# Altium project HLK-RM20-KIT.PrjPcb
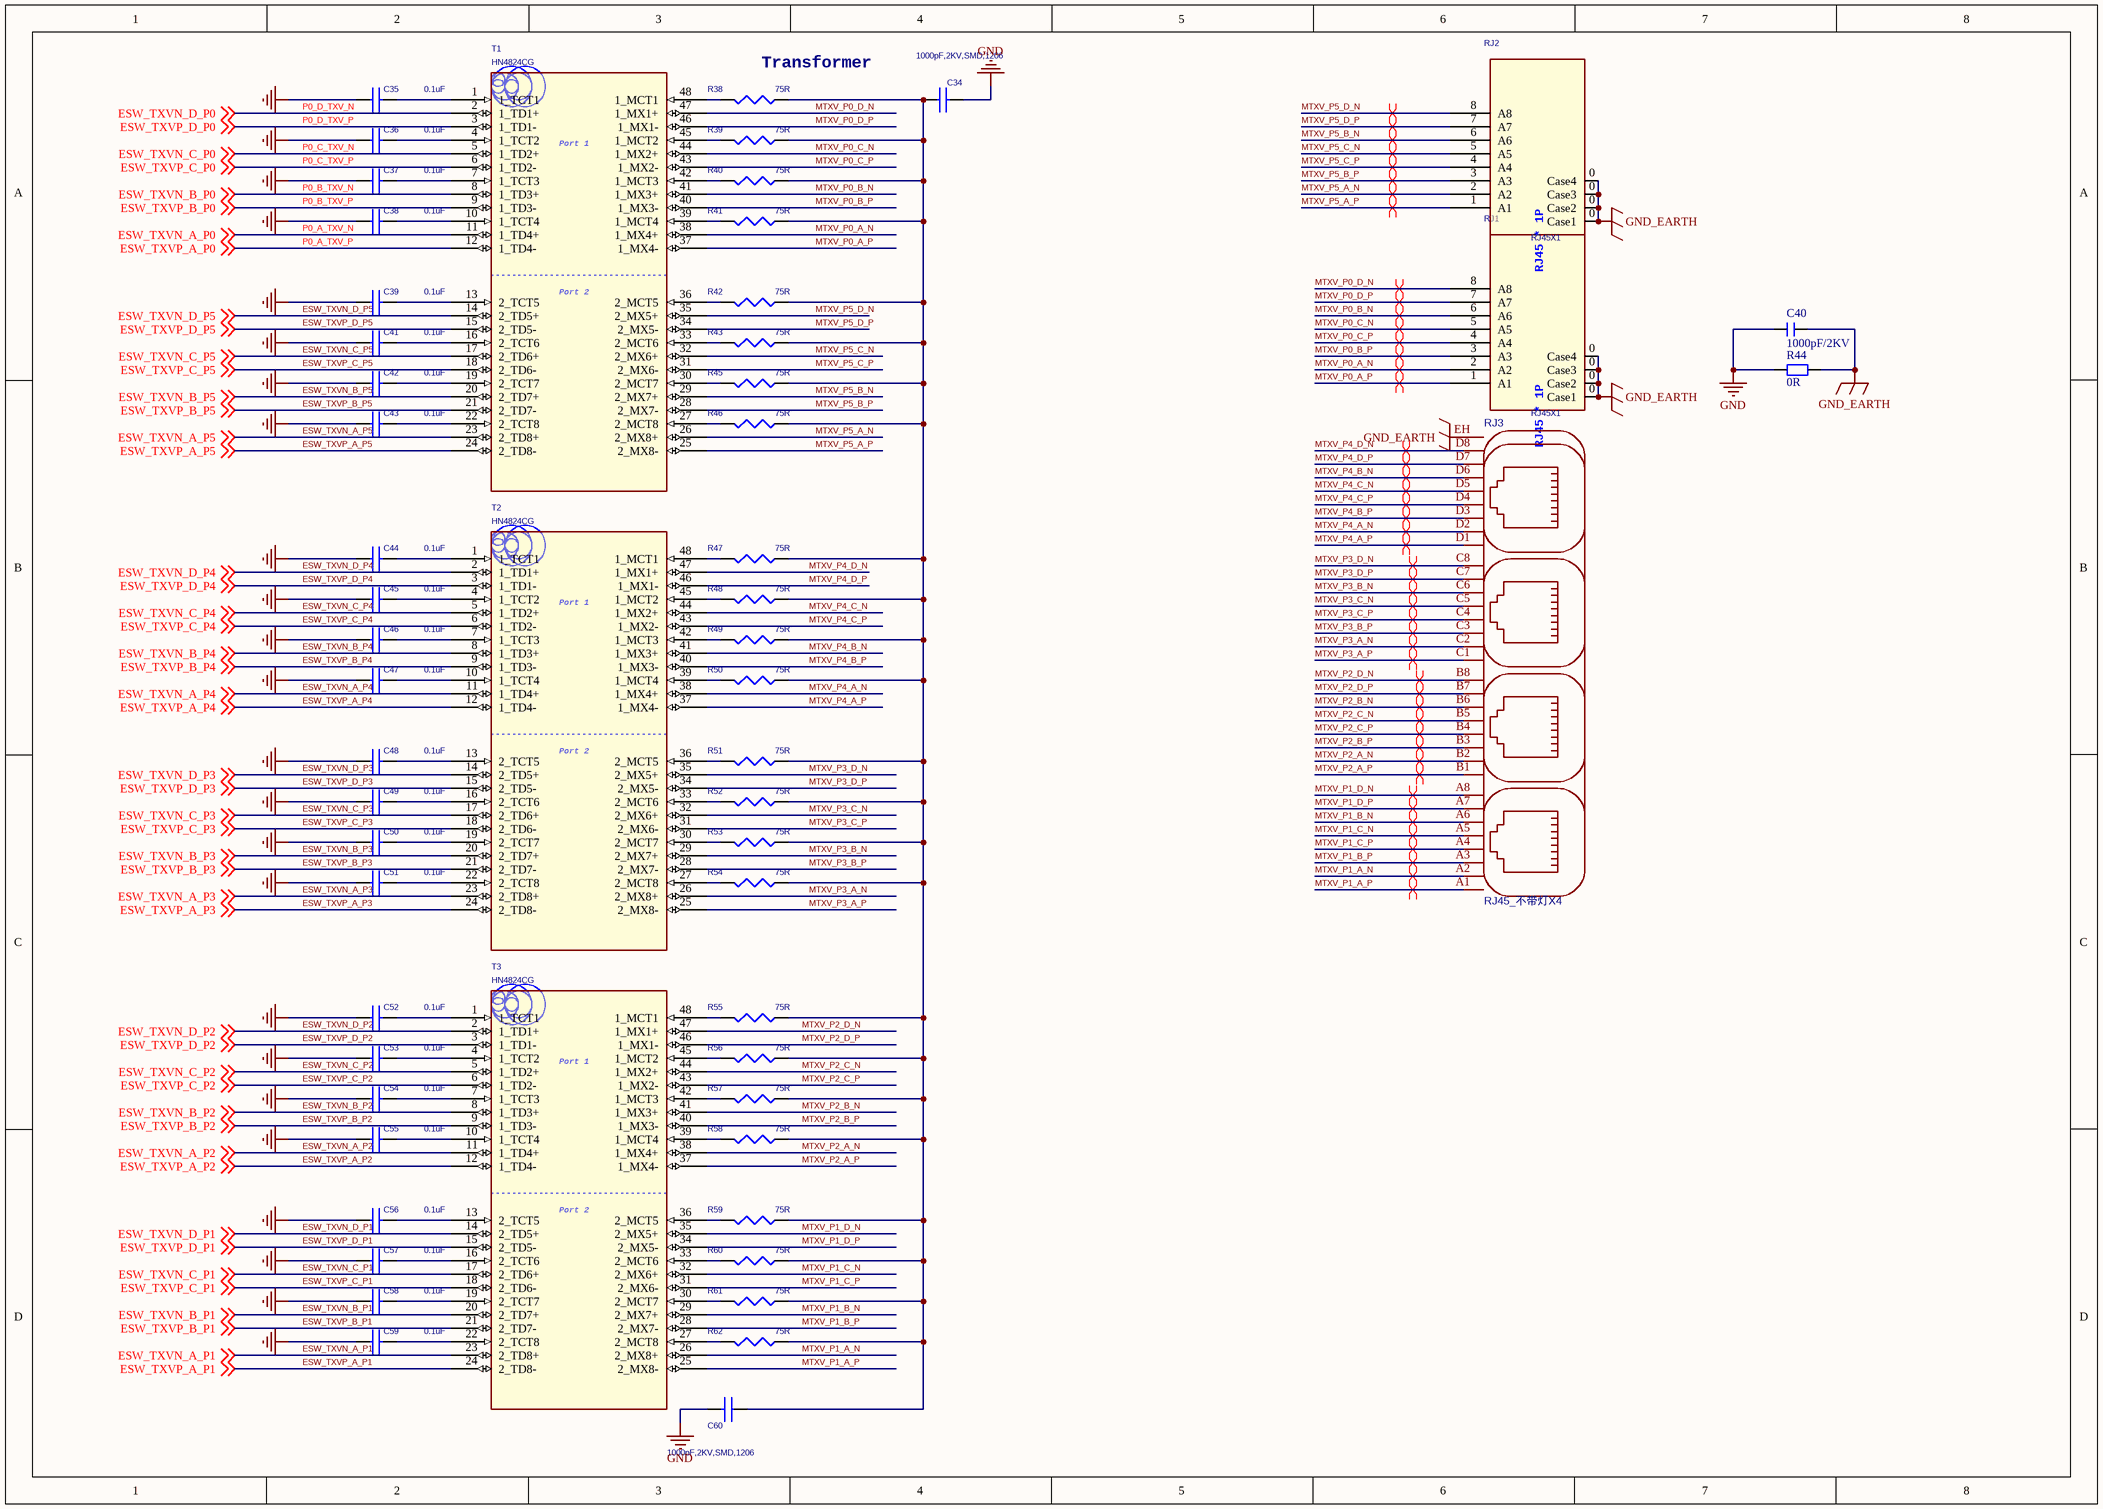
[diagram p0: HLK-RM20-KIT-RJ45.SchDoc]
4 sheets, 212 parts. Net scope: global (net labels, ports and power ports of the same name join across sheets).
Board file: HLK-RM20-KIT.PcbDoc
Sheets:
  HLK-RM20-KIT-RJ45.SchDoc
  HLK-RM20-KIT-4G.SchDoc
  HLK-RM20-KIT-5G.SchDoc
  HLK-RM20-KIT-POWER_LED.SchDoc

## Sheet HLK-RM20-KIT-RJ45.SchDoc
size A3

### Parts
C34  1000pF,2KV,SMD,1206  [C 1206_L]
C35  0.1uF  [C 0402_L]
C36  0.1uF  [C 0402_L]
C37  0.1uF  [C 0402_L]
C38  0.1uF  [C 0402_L]
C39  0.1uF  [C 0402_L]
C40  1000pF/2KV  [C 1206_L]
C41  0.1uF  [C 0402_L]
C42  0.1uF  [C 0402_L]
C43  0.1uF  [C 0402_L]
C44  0.1uF  [C 0402_L]
C45  0.1uF  [C 0402_L]
C46  0.1uF  [C 0402_L]
C47  0.1uF  [C 0402_L]
C48  0.1uF  [C 0402_L]
C49  0.1uF  [C 0402_L]
C50  0.1uF  [C 0402_L]
C51  0.1uF  [C 0402_L]
C52  0.1uF  [C 0402_L]
C53  0.1uF  [C 0402_L]
C54  0.1uF  [C 0402_L]
C55  0.1uF  [C 0402_L]
C56  0.1uF  [C 0402_L]
C57  0.1uF  [C 0402_L]
C58  0.1uF  [C 0402_L]
C59  0.1uF  [C 0402_L]
C60  1000pF,2KV,SMD,1206  [C 1206_L]
R38  75R  [R 0402_L]
R39  75R  [R 0402_L]
R40  75R  [R 0402_L]
R41  75R  [R 0402_L]
R42  75R  [R 0402_L]
R43  75R  [R 0402_L]
R44  0R  [R 1206_L]
R45  75R  [R 0402_L]
R46  75R  [R 0402_L]
R47  75R  [R 0402_L]
R48  75R  [R 0402_L]
R49  75R  [R 0402_L]
R50  75R  [R 0402_L]
R51  75R  [R 0402_L]
R52  75R  [R 0402_L]
R53  75R  [R 0402_L]
R54  75R  [R 0402_L]
R55  75R  [R 0402_L]
R56  75R  [R 0402_L]
R57  75R  [R 0402_L]
R58  75R  [R 0402_L]
R59  75R  [R 0402_L]
R60  75R  [R 0402_L]
R61  75R  [R 0402_L]
R62  75R  [R 0402_L]
RJ1  RJ45X1  [RJ45_网口不带灯X1]
RJ2  RJ45X1  [RJ45_网口不带灯X1]
RJ3  RJ45_不带灯X4  [RJ45_网口不带灯X4]
T1  HN4824CG  [TRANSFORMER/48P/SMD/GS5014LF]
T2  HN4824CG  [TRANSFORMER/48P/SMD/GS5014LF]
T3  HN4824CG  [TRANSFORMER/48P/SMD/GS5014LF]

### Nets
GND: C34.2 C35.1 C36.1 C37.1 C38.1 C39.1 C40.1 C41.1 C42.1 C43.1 C44.1 C45.1 C46.1 C47.1 C48.1 C49.1 C50.1 C51.1 C52.1 C53.1 C54.1 C55.1 C56.1 C57.1 C58.1 C59.1 C60.2 R44.1
GND_EARTH: C40.2 R44.2 RJ1.0(Case1) RJ2.0(Case1) RJ3.EH
ESW_TXVN_A_P1: T3.23(2_TD8+) ; off-sheet ESW_TXVN_A_P1  [project net ESW_A_P1_TXV_N]
ESW_TXVN_A_P2: T3.11(1_TD4+) ; off-sheet ESW_TXVN_A_P2  [project net ESW_A_P2_TXV_N]
ESW_TXVN_A_P3: T2.23(2_TD8+) ; off-sheet ESW_TXVN_A_P3  [project net ESW_A_P3_TXV_N]
ESW_TXVN_A_P4: T2.11(1_TD4+) ; off-sheet ESW_TXVN_A_P4  [project net ESW_A_P4_TXV_N]
ESW_TXVN_A_P5: T1.23(2_TD8+) ; off-sheet ESW_TXVN_A_P5  [project net ESW_A_P5_TXV_N]
ESW_TXVN_B_P1: T3.20(2_TD7+) ; off-sheet ESW_TXVN_B_P1  [project net ESW_B_P1_TXV_N]
ESW_TXVN_B_P2: T3.8(1_TD3+) ; off-sheet ESW_TXVN_B_P2  [project net ESW_B_P2_TXV_N]
ESW_TXVN_B_P3: T2.20(2_TD7+) ; off-sheet ESW_TXVN_B_P3  [project net ESW_B_P3_TXV_N]
ESW_TXVN_B_P4: T2.8(1_TD3+) ; off-sheet ESW_TXVN_B_P4  [project net ESW_B_P4_TXV_N]
ESW_TXVN_B_P5: T1.20(2_TD7+) ; off-sheet ESW_TXVN_B_P5  [project net ESW_B_P5_TXV_N]
ESW_TXVN_C_P1: T3.17(2_TD6+) ; off-sheet ESW_TXVN_C_P1  [project net ESW_C_P1_TXV_N]
ESW_TXVN_C_P2: T3.5(1_TD2+) ; off-sheet ESW_TXVN_C_P2  [project net ESW_C_P2_TXV_N]
ESW_TXVN_C_P3: T2.17(2_TD6+) ; off-sheet ESW_TXVN_C_P3  [project net ESW_C_P3_TXV_N]
ESW_TXVN_C_P4: T2.5(1_TD2+) ; off-sheet ESW_TXVN_C_P4  [project net ESW_C_P4_TXV_N]
ESW_TXVN_C_P5: T1.17(2_TD6+) ; off-sheet ESW_TXVN_C_P5  [project net ESW_C_P5_TXV_N]
ESW_TXVN_D_P1: T3.14(2_TD5+) ; off-sheet ESW_TXVN_D_P1  [project net ESW_D_P1_TXV_N]
ESW_TXVN_D_P2: T3.2(1_TD1+) ; off-sheet ESW_TXVN_D_P2  [project net ESW_D_P2_TXV_N]
ESW_TXVN_D_P3: T2.14(2_TD5+) ; off-sheet ESW_TXVN_D_P3  [project net ESW_D_P3_TXV_N]
ESW_TXVN_D_P4: T2.2(1_TD1+) ; off-sheet ESW_TXVN_D_P4  [project net ESW_D_P4_TXV_N]
ESW_TXVN_D_P5: T1.14(2_TD5+) ; off-sheet ESW_TXVN_D_P5  [project net ESW_D_P5_TXV_N]
ESW_TXVP_A_P1: T3.24(2_TD8-) ; off-sheet ESW_TXVP_A_P1  [project net ESW_A_P1_TXV_P]
ESW_TXVP_A_P2: T3.12(1_TD4-) ; off-sheet ESW_TXVP_A_P2  [project net ESW_A_P2_TXV_P]
ESW_TXVP_A_P3: T2.24(2_TD8-) ; off-sheet ESW_TXVP_A_P3  [project net ESW_A_P3_TXV_P]
ESW_TXVP_A_P4: T2.12(1_TD4-) ; off-sheet ESW_TXVP_A_P4  [project net ESW_A_P4_TXV_P]
ESW_TXVP_A_P5: T1.24(2_TD8-) ; off-sheet ESW_TXVP_A_P5  [project net ESW_A_P5_TXV_P]
ESW_TXVP_B_P1: T3.21(2_TD7-) ; off-sheet ESW_TXVP_B_P1  [project net ESW_B_P1_TXV_P]
ESW_TXVP_B_P2: T3.9(1_TD3-) ; off-sheet ESW_TXVP_B_P2  [project net ESW_B_P2_TXV_P]
ESW_TXVP_B_P3: T2.21(2_TD7-) ; off-sheet ESW_TXVP_B_P3  [project net ESW_B_P3_TXV_P]
ESW_TXVP_B_P4: T2.9(1_TD3-) ; off-sheet ESW_TXVP_B_P4  [project net ESW_B_P4_TXV_P]
ESW_TXVP_B_P5: T1.21(2_TD7-) ; off-sheet ESW_TXVP_B_P5  [project net ESW_B_P5_TXV_P]
ESW_TXVP_C_P1: T3.18(2_TD6-) ; off-sheet ESW_TXVP_C_P1  [project net ESW_C_P1_TXV_P]
ESW_TXVP_C_P2: T3.6(1_TD2-) ; off-sheet ESW_TXVP_C_P2  [project net ESW_C_P2_TXV_P]
ESW_TXVP_C_P3: T2.18(2_TD6-) ; off-sheet ESW_TXVP_C_P3  [project net ESW_C_P3_TXV_P]
ESW_TXVP_C_P4: T2.6(1_TD2-) ; off-sheet ESW_TXVP_C_P4  [project net ESW_C_P4_TXV_P]
ESW_TXVP_C_P5: T1.18(2_TD6-) ; off-sheet ESW_TXVP_C_P5  [project net ESW_C_P5_TXV_P]
ESW_TXVP_D_P1: T3.15(2_TD5-) ; off-sheet ESW_TXVP_D_P1  [project net ESW_D_P1_TXV_P]
ESW_TXVP_D_P2: T3.3(1_TD1-) ; off-sheet ESW_TXVP_D_P2  [project net ESW_D_P2_TXV_P]
ESW_TXVP_D_P3: T2.15(2_TD5-) ; off-sheet ESW_TXVP_D_P3  [project net ESW_D_P3_TXV_P]
ESW_TXVP_D_P4: T2.3(1_TD1-) ; off-sheet ESW_TXVP_D_P4  [project net ESW_D_P4_TXV_P]
ESW_TXVP_D_P5: T1.15(2_TD5-) ; off-sheet ESW_TXVP_D_P5  [project net ESW_D_P5_TXV_P]
MTXV_P0_A_N: RJ1.2(A2) T1.38(1_MX4+)
MTXV_P0_A_P: RJ1.1(A1) T1.37(1_MX4-)
MTXV_P0_B_N: RJ1.6(A6) T1.41(1_MX3+)
MTXV_P0_B_P: RJ1.3(A3) T1.40(1_MX3-)
MTXV_P0_C_N: RJ1.5(A5) T1.44(1_MX2+)
MTXV_P0_C_P: RJ1.4(A4) T1.43(1_MX2-)
MTXV_P0_D_N: RJ1.8(A8) T1.47(1_MX1+)
MTXV_P0_D_P: RJ1.7(A7) T1.46(1_MX1-)
MTXV_P1_A_N: RJ3.A2 T3.26(2_MX8+)
MTXV_P1_A_P: RJ3.A1 T3.25(2_MX8-)
MTXV_P1_B_N: RJ3.A6 T3.29(2_MX7+)
MTXV_P1_B_P: RJ3.A3 T3.28(2_MX7-)
MTXV_P1_C_N: RJ3.A5 T3.32(2_MX6+)
MTXV_P1_C_P: RJ3.A4 T3.31(2_MX6-)
MTXV_P1_D_N: RJ3.A8 T3.35(2_MX5+)
MTXV_P1_D_P: RJ3.A7 T3.34(2_MX5-)
MTXV_P2_A_N: RJ3.B2 T3.38(1_MX4+)
MTXV_P2_A_P: RJ3.B1 T3.37(1_MX4-)
MTXV_P2_B_N: RJ3.B6 T3.41(1_MX3+)
MTXV_P2_B_P: RJ3.B3 T3.40(1_MX3-)
MTXV_P2_C_N: RJ3.B5 T3.44(1_MX2+)
MTXV_P2_C_P: RJ3.B4 T3.43(1_MX2-)
MTXV_P2_D_N: RJ3.B8 T3.47(1_MX1+)
MTXV_P2_D_P: RJ3.B7 T3.46(1_MX1-)
MTXV_P3_A_N: RJ3.C2 T2.26(2_MX8+)
MTXV_P3_A_P: RJ3.C1 T2.25(2_MX8-)
MTXV_P3_B_N: RJ3.C6 T2.29(2_MX7+)
MTXV_P3_B_P: RJ3.C3 T2.28(2_MX7-)
MTXV_P3_C_N: RJ3.C5 T2.32(2_MX6+)
MTXV_P3_C_P: RJ3.C4 T2.31(2_MX6-)
MTXV_P3_D_N: RJ3.C8 T2.35(2_MX5+)
MTXV_P3_D_P: RJ3.C7 T2.34(2_MX5-)
MTXV_P4_A_N: RJ3.D2 T2.38(1_MX4+)
MTXV_P4_A_P: RJ3.D1 T2.37(1_MX4-)
MTXV_P4_B_N: RJ3.D6 T2.41(1_MX3+)
MTXV_P4_B_P: RJ3.D3 T2.40(1_MX3-)
MTXV_P4_C_N: RJ3.D5 T2.44(1_MX2+)
MTXV_P4_C_P: RJ3.D4 T2.43(1_MX2-)
MTXV_P4_D_N: RJ3.D8 T2.47(1_MX1+)
MTXV_P4_D_P: RJ3.D7 T2.46(1_MX1-)
MTXV_P5_A_N: RJ2.2(A2) T1.26(2_MX8+)
MTXV_P5_A_P: RJ2.1(A1) T1.25(2_MX8-)
MTXV_P5_B_N: RJ2.6(A6) T1.29(2_MX7+)
MTXV_P5_B_P: RJ2.3(A3) T1.28(2_MX7-)
MTXV_P5_C_N: RJ2.5(A5) T1.32(2_MX6+)
MTXV_P5_C_P: RJ2.4(A4) T1.31(2_MX6-)
MTXV_P5_D_N: RJ2.8(A8) T1.35(2_MX5+)
MTXV_P5_D_P: RJ2.7(A7) T1.34(2_MX5-)
P0_A_TXV_N: T1.11(1_TD4+) ; off-sheet ESW_TXVN_A_P0  [also labelled ESW_TXVN_A_P0]
P0_A_TXV_P: T1.12(1_TD4-) ; off-sheet ESW_TXVP_A_P0  [also labelled ESW_TXVP_A_P0]
P0_B_TXV_N: T1.8(1_TD3+) ; off-sheet ESW_TXVN_B_P0  [also labelled ESW_TXVN_B_P0]
P0_B_TXV_P: T1.9(1_TD3-) ; off-sheet ESW_TXVP_B_P0  [also labelled ESW_TXVP_B_P0]
P0_C_TXV_N: T1.5(1_TD2+) ; off-sheet ESW_TXVN_C_P0  [also labelled ESW_TXVN_C_P0]
P0_C_TXV_P: T1.6(1_TD2-) ; off-sheet ESW_TXVP_C_P0  [also labelled ESW_TXVP_C_P0]
P0_D_TXV_N: T1.2(1_TD1+) ; off-sheet ESW_TXVN_D_P0  [also labelled ESW_TXVN_D_P0]
P0_D_TXV_P: T1.3(1_TD1-) ; off-sheet ESW_TXVP_D_P0  [also labelled ESW_TXVP_D_P0]
NetC34_1: C34.1 C60.1 R38.1 R39.1 R40.1 R41.1 R42.1 R43.1 R45.1 R46.1 R47.1 R48.1 R49.1 R50.1 R51.1 R52.1 R53.1 R54.1 R55.1 R56.1 R57.1 R58.1 R59.1 R60.1 R61.1 R62.1
NetC35_2: C35.2 T1.1(1_TCT1)
NetC36_2: C36.2 T1.4(1_TCT2)
NetC37_2: C37.2 T1.7(1_TCT3)
NetC38_2: C38.2 T1.10(1_TCT4)
NetC39_2: C39.2 T1.13(2_TCT5)
NetC41_2: C41.2 T1.16(2_TCT6)
NetC42_2: C42.2 T1.19(2_TCT7)
NetC43_2: C43.2 T1.22(2_TCT8)
NetC44_2: C44.2 T2.1(1_TCT1)
NetC45_2: C45.2 T2.4(1_TCT2)
NetC46_2: C46.2 T2.7(1_TCT3)
NetC47_2: C47.2 T2.10(1_TCT4)
NetC48_2: C48.2 T2.13(2_TCT5)
NetC49_2: C49.2 T2.16(2_TCT6)
NetC50_2: C50.2 T2.19(2_TCT7)
NetC51_2: C51.2 T2.22(2_TCT8)
NetC52_2: C52.2 T3.1(1_TCT1)
NetC53_2: C53.2 T3.4(1_TCT2)
NetC54_2: C54.2 T3.7(1_TCT3)
NetC55_2: C55.2 T3.10(1_TCT4)
NetC56_2: C56.2 T3.13(2_TCT5)
NetC57_2: C57.2 T3.16(2_TCT6)
NetC58_2: C58.2 T3.19(2_TCT7)
NetC59_2: C59.2 T3.22(2_TCT8)
NetR38_2: R38.2 T1.48(1_MCT1)
NetR39_2: R39.2 T1.45(1_MCT2)
NetR40_2: R40.2 T1.42(1_MCT3)
NetR41_2: R41.2 T1.39(1_MCT4)
NetR42_2: R42.2 T1.36(2_MCT5)
NetR43_2: R43.2 T1.33(2_MCT6)
NetR45_2: R45.2 T1.30(2_MCT7)
NetR46_2: R46.2 T1.27(2_MCT8)
NetR47_2: R47.2 T2.48(1_MCT1)
NetR48_2: R48.2 T2.45(1_MCT2)
NetR49_2: R49.2 T2.42(1_MCT3)
NetR50_2: R50.2 T2.39(1_MCT4)
NetR51_2: R51.2 T2.36(2_MCT5)
NetR52_2: R52.2 T2.33(2_MCT6)
NetR53_2: R53.2 T2.30(2_MCT7)
NetR54_2: R54.2 T2.27(2_MCT8)
NetR55_2: R55.2 T3.48(1_MCT1)
NetR56_2: R56.2 T3.45(1_MCT2)
NetR57_2: R57.2 T3.42(1_MCT3)
NetR58_2: R58.2 T3.39(1_MCT4)
NetR59_2: R59.2 T3.36(2_MCT5)
NetR60_2: R60.2 T3.33(2_MCT6)
NetR61_2: R61.2 T3.30(2_MCT7)
NetR62_2: R62.2 T3.27(2_MCT8)

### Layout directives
differential pair: MTXV_P0_A_N, MTXV_P0_A_P, MTXV_P0_B_N, MTXV_P0_B_P, MTXV_P0_C_N, MTXV_P0_C_P, MTXV_P0_D_N, MTXV_P0_D_P, MTXV_P1_A_N, MTXV_P1_A_P, MTXV_P1_B_N, MTXV_P1_B_P, MTXV_P1_C_N, MTXV_P1_C_P, MTXV_P1_D_N, MTXV_P1_D_P, MTXV_P2_A_N, MTXV_P2_A_P, MTXV_P2_B_N, MTXV_P2_B_P, MTXV_P2_C_N, MTXV_P2_C_P, MTXV_P2_D_N, MTXV_P2_D_P, MTXV_P3_A_N, MTXV_P3_A_P, MTXV_P3_B_N, MTXV_P3_B_P, MTXV_P3_C_N, MTXV_P3_C_P, MTXV_P3_D_N, MTXV_P3_D_P, MTXV_P4_A_N, MTXV_P4_A_P, MTXV_P4_B_N, MTXV_P4_B_P, MTXV_P4_C_N, MTXV_P4_C_P, MTXV_P4_D_N, MTXV_P4_D_P, MTXV_P5_A_N, MTXV_P5_A_P, MTXV_P5_B_N, MTXV_P5_B_P, MTXV_P5_C_N, MTXV_P5_C_P, MTXV_P5_D_N, MTXV_P5_D_P

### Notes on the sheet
- (near R38) Transformer

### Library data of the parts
C34 C60 = CAP NP_Dup1: Cap, HighVolt, SMD 1206, 2KV; Manufacturer: Arcotromics; Class: 0C-HighVolt; Key: 3162U-N14-V11-#409; BOM_Class: RJ45; HYP_Type: (C; By: Ralink
C35-C39 C41-C43 C48-C53 C56 C57 = 0.1UF/25V_+80%-20%_CC_S0603: Cap, MLCC, 0402, Y5V, 16V; Manufacturer: 地穝; Part Number: 100-110-03400; V1: 25V +80% -20%; P/N: 26-400-311104; Class: 0C-0402; Key: 3162U-N14-V11-#478; BOM_Class: RJ45; HYP_Type: (C; By: Ralink
C40 = C: 无极性贴片电容; 版权归属: 源创客
C44-C47 C54 C55 C58 C59 = 0.1UF/25V_+80%-20%_CC_S0603: Cap, MLCC, 0402, Y5V, 16V; Part Number: 100-110-03400; Manufacturer: 地穝; V1: 25V +80% -20%; P/N: 26-400-311104; By: Ralink; HYP_Type: (C; BOM_Class: RJ45; Key: 3162U-N14-V11-#478; Class: 0C-0402
R38 R39 R42 R43 = R75_1%_S0603: Resistor, 0402, 5%; Manufacturer: 驾м; Part Number: 110-110-03300; V1: 1% 1/16W; P/N: 21-201-627501; SDTSourceLibName: C:\WINDOWS\TEMP\DEVICE1.LIB; HYP_Type: (R; BOM_Class: RJ45; By: Ralink; Key: 3162U-N14-V11-#345; Class: 1R-0402
R40 R45 = R75_1%_S0603: Resistor, 0402, 5%; Manufacturer: 驾м; Part Number: 110-110-03300; V1: 1% 1/16W; P/N: 21-201-627501; SDTSourceLibName: C:\WINDOWS\TEMP\DEVICE1.LIB; By: Ralink; BOM_Class: RJ45; HYP_Type: (R; Key: 3162U-N14-V11-#345; Class: 1R-0402
R41 R46 = R75_1%_S0603: Resistor, 0402, 5%; Part Number: 110-110-03300; Manufacturer: 驾м; V1: 1% 1/16W; P/N: 21-201-627501; SDTSourceLibName: C:\WINDOWS\TEMP\DEVICE1.LIB; Class: 1R-0402; Key: 3162U-N14-V11-#345; HYP_Type: (R; BOM_Class: RJ45; By: Ralink
R44 = R: 贴片电阻; 版权归属: 源创客
R47 R50 R53 R58-R60 R62 = R75_1%_S0603: Resistor, SMD 0402, 5%; Manufacturer: 驾м; Part Number: 110-110-03300; V1: 5% 1/4W; P/N: 21-201-627501; SDTSourceLibName: C:\WINDOWS\TEMP\SCH.LIB; By: Ralink; BOM_Class: RJ45; HYP_Type: (R; Key: 3162U-N14-V11-#345; Class: 1R-0402
R48 R49 R51 R52 R54-R57 R61 = R75_1%_S0603: Resistor, SMD 0402, 5%; Part Number: 110-110-03300; Manufacturer: 驾м; V1: 5% 1/4W; P/N: 21-201-627501; SDTSourceLibName: C:\WINDOWS\TEMP\SCH.LIB; Class: 1R-0402; Key: 3162U-N14-V11-#345; HYP_Type: (R; BOM_Class: RJ45; By: Ralink
RJ1 RJ2 = RJ45X1_4: Manufacturer: 救┹; Manufacturer's Part Number: PJ-A1-BXBH-FDNNN-1; Part Number: 214411*12311105
RJ3 = RJ45_不带灯X4: BOM_Manufacturer: CONNFLY; BOM_Manufacturer Part: DS1129-02-S80BP; subpart_no: 3
T1-T3 = XMER 2P G2PM109N

## Sheet HLK-RM20-KIT-4G.SchDoc
size A4
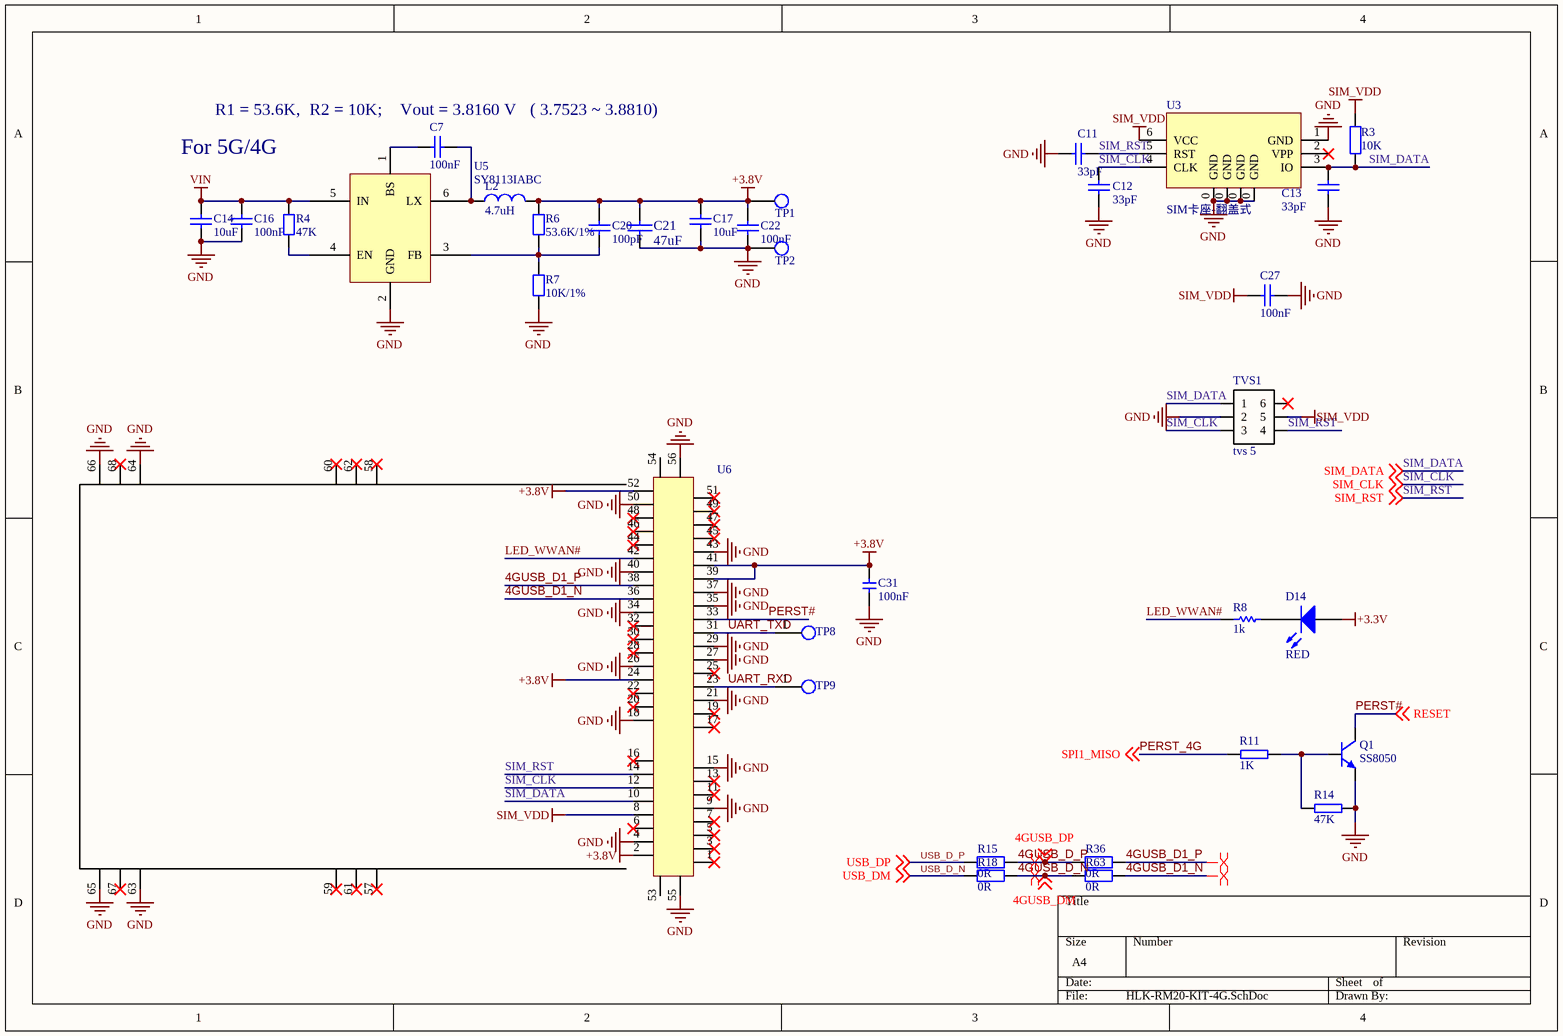
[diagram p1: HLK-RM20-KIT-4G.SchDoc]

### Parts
C7  100nF  [C 0402_L]
C11  33pF  [C 0402_L]
C12  33pF  [C 0402_L]
C13  33pF  [C 0402_L]
C14  10uF  [C 0805_L]
C16  100nF  [C 0402_L]
C17  10uF  [C 0603_L]
C20  100pF  [C 0402_L]
C21  47uF  [C 1206_l]
C22  100nF  [C 0402_L]
C27  100nF  [C 0402_L]
C31  100nF  [C 0402_L]
D14  RED  [LED 3MM-G]
L2  4.7uH  [L 5*5]
Q1  SS8050  [SOT23-3N]
R3  10K  [R 0402_L]
R4  47K  [R 0402_L]
R6  53.6K/1%  [R 0402_L]
R7  10K/1%  [R 0402_L]
R8  value 1k  [R 0402_L]  (hidden comment: Res1)
R11  1K  [R 0402_L]
R14  47K  [R 0402_L]
R15  0R  [R 0402_L]
R18  0R  [R 0402_L]
R36  0R  [R 0402_L]
R63  0R  [R 0402_L]
TP1  测试点  [TEST 1.6]  (value not drawn)
TP2  测试点  [TEST 1.6]  (value not drawn)
TP8  TP  [TEST 1]  (value not drawn)
TP9  TP  [TEST 1]  (value not drawn)
TVS1  tvs 5  [TVS-6]
U3  SIM卡座-翻盖式  [NANOSIM]
U5  SY8113IABC  [SOT23-6N]
U6  (no value)  [MiniPCIE全卡 卡座]

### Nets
+3.3V: D14.1(A)
+3.8V: C17.1 C20.2 C21.2 C22.1 C31.1 L2.2 R6.1 TP1.1 U6.2 U6.24 U6.39 U6.41 U6.52
GND: C11.2 C12.2 C13.2 C14.1 C16.2 C17.2 C21.1 C22.2 C27.1 C31.2 Q1.2(E) R7.2 R14.1 TP2.1 TVS1.2 U3.0(GND) U3.1(GND) U5.2(GND) U6.4 U6.9 U6.15 U6.18 U6.21 U6.26 U6.27 U6.29 U6.34 U6.35 U6.37 U6.40 U6.43 U6.50 U6.55 U6.56 U6.63 U6.64 U6.65 U6.66
SIM_VDD: C27.2 R3.2 TVS1.5 U3.6(VCC) U6.8  [project net SIM2_VDD]
VIN: C14.2 C16.1 R4.1 U5.5(IN)
4GUSB_D1_N: R63.1 U6.36
4GUSB_D1_P: R36.1 U6.38
4GUSB_D_N: R18.1 R63.2 ; off-sheet 4GUSB_DM  [also labelled 4GUSB_DM]
4GUSB_D_P: R15.1 R36.2 ; off-sheet 4GUSB_DP  [also labelled 4GUSB_DP]
LED_WWAN#: R8.2 U6.42
PERST#: Q1.3(C) U6.33 ; off-sheet RESET  [also labelled RESET]
PERST_4G: R11.2 ; off-sheet SPI1_MISO  [also labelled SPI1_MISO]
SIM_CLK: C12.1 TVS1.3 U3.4(CLK) U6.12 ; off-sheet SIM_CLK  [project net SIM2_CLK]
SIM_DATA: C13.1 R3.1 TVS1.1 U3.3(IO) U6.10 ; off-sheet SIM_DATA  [project net SIM2_DATA]
SIM_RST: C11.1 TVS1.4 U3.5(RST) U6.14 ; off-sheet SIM_RST  [project net SIM2_RST]
UART_RXD: TP9.1 U6.23
UART_TXD: TP8.1 U6.31
USB_D_N: R18.2 ; off-sheet USB_DM  [also labelled USB_DM]
USB_D_P: R15.2 ; off-sheet USB_DP  [also labelled USB_DP]
NetC7_1: C7.1 U5.1(BS)
NetC7_2: C7.2 L2.1 U5.6(LX)
NetC20_1: C20.1 R6.2 R7.1 U5.3(FB)
NetD14_2: D14.2(K) R8.1
NetQ1_1: Q1.1(B) R11.1 R14.2
NetR4_2: R4.2 U5.4(EN)

Not connected (* = marked no-connect by the designer): TVS1 6*; U3 2(VPP)*; U6 1(0)* 3* 5* 6* 7* 11* 13* 16* 17* 19* 20* 22* 25* 28* 30* 32* 44* 45* 46* 47* 48* 49* 51* 53 54 57* 58* 59* 60* 61* 62* 67* 68*

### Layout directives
differential pair: 4GUSB_D1_N, 4GUSB_D1_P, 4GUSB_D_N, 4GUSB_D_P

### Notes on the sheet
- (near C7) R1 = 53.6K,  R2 = 10K;    Vout = 3.8160 V   ( 3.7523 ~ 3.8810)
- For 5G/4G

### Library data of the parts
C7 C11-C13 C16 C17 C22 C27 = Cap: Capacitor; 物料名称: 贴片电容; 物料编码: 3.01.04.0056
C14 = Cap: Capacitor; Manufacturer: Generic Components; Class: Passive; Value: 100pF
C20 = Cap: Capacitor; Manufacturer: Generic Components; Class: Passive
C21 = CAP: Capacitor
C31 = CAP1: C?
D14 = LED0: 贴片发光二极管
L2 = LineInductors
Q1 = 8050-SMD: 高频放大-NPN型; 版权归属: 源创客; 属性: 40V 1.5A 1W 100MHZ
R3 R15 R18 R36 R63 = Res2: Resistor
R4 R6 R7 = R: 贴片电阻; 版权归属: 源创客
R8 = Res1: Resistor
R11 R14 = RES1: R?
TP1 TP2 = TP
TVS1 = Tvs
U3 = SIM座
U5 = SY8113IABC: VIN=4.5-18V  I=3A
U6 = Component_1

## Sheet HLK-RM20-KIT-5G.SchDoc
size A4
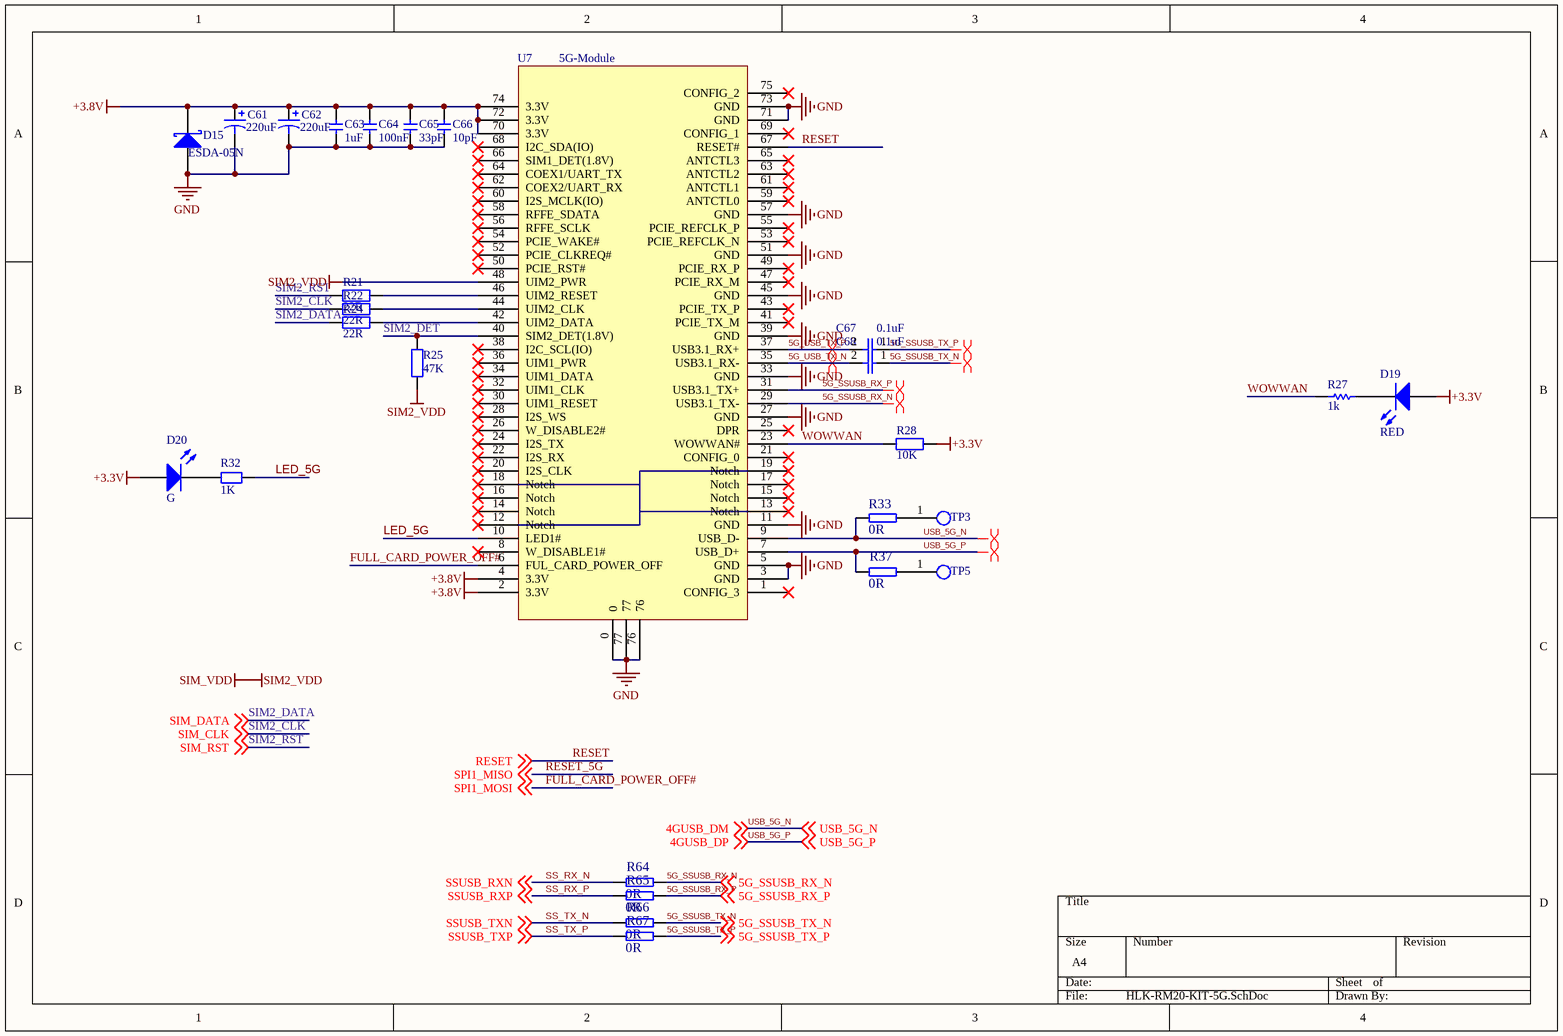
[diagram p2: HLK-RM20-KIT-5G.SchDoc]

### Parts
C61  220uF  [CT 6*6 - R]
C62  220uF  [CT 6*6 - R]
C63  1uF  [C 0402_L]
C64  100nF  [C 0402_L]
C65  33pF  [C 0402_L]
C66  10pF  [C 0402_L]
C67  0.1uF  [C 0402_L]
C68  0.1uF  [C 0402_L]
D15  ESDA-05N  [ESD0402]
D19  RED  [LED 0603B-L]
D20  G  [LED 3MM-G]
R21  22R  [R 0402_L]
R22  22R  [R 0402_L]
R24  22R  [R 0402_L]
R25  47K  [R 0402_L]
R27  1K  [R 0402_L]
R28  10K  [R 0402_L]
R32  1K  [R 0402_L]
R33  0R  [R 0402_L]
R37  0R  [R 0402_L]
R64  0R  [R 0402_L]
R65  0R  [R 0402_L]
R66  0R  [R 0402_L]
R67  0R  [R 0402_L]
TP3  TP  [TEST 1]  (value not drawn)
TP5  TP  [TEST 1]  (value not drawn)
U7  5G-Module  [5G_RM500Q-GL]

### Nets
+3.3V: D19.1(A) D20.1(A) R28.2
+3.8V: C61.1 C62.1 C63.1 C64.1 C65.1 C66.1 D15.2(K) U7.2(3.3V) U7.4(3.3V) U7.70(3.3V) U7.72(3.3V) U7.74(3.3V)
GND: C61.2 C62.2 C63.2 C64.2 C65.2 C66.2 D15.1(A) U7.0 U7.3(GND) U7.5(GND) U7.11(GND) U7.27(GND) U7.33(GND) U7.39(GND) U7.45(GND) U7.51(GND) U7.57(GND) U7.71(GND) U7.73(GND) U7.76 U7.77
SIM2_VDD: R25.1 U7.48(UIM2_PWR)  [also labelled SIM_VDD]
4GUSB_DM: R33.2 U7.9(USB_D-) ; off-sheet USB_5G_N, off-sheet 4GUSB_DM  [also labelled USB_5G_N]  [project net 4GUSB_D_N]
4GUSB_DP: R37.2 U7.7(USB_D+) ; off-sheet USB_5G_P, off-sheet 4GUSB_DP  [also labelled USB_5G_P]  [project net 4GUSB_D_P]
5G_SSUSB_RX_N: R64.1 U7.29(USB3.1_TX-) ; off-sheet 5G_SSUSB_RX_N
5G_SSUSB_RX_P: R65.1 U7.31(USB3.1_TX+) ; off-sheet 5G_SSUSB_RX_P
5G_SSUSB_TX_N: C68.1 R66.1 ; off-sheet 5G_SSUSB_TX_N
5G_SSUSB_TX_P: C67.1 R67.1 ; off-sheet 5G_SSUSB_TX_P
5G_USB_TX_N: C68.2 U7.35(USB3.1_RX-)
5G_USB_TX_P: C67.2 U7.37(USB3.1_RX+)
FULL_CARD_POWER_OFF#: U7.6(FUL_CARD_POWER_OFF) ; off-sheet SPI1_MOSI  [also labelled SPI1_MOSI]
LED_5G: R32.1 U7.10(LED1#)
RESET: U7.67(RESET#) ; off-sheet RESET  [project net PERST#]
SIM2_CLK: R22.1 ; off-sheet SIM_CLK  [also labelled SIM_CLK]
SIM2_DATA: R24.1 ; off-sheet SIM_DATA  [also labelled SIM_DATA]
SIM2_DET: R25.2 U7.40(SIM2_DET(1.8V))
SIM2_RST: R21.1 ; off-sheet SIM_RST  [also labelled SIM_RST]
SS_RX_N: R64.2 ; off-sheet SSUSB_RXN  [also labelled SSUSB_RXN]
SS_RX_P: R65.2 ; off-sheet SSUSB_RXP  [also labelled SSUSB_RXP]
SS_TX_N: R66.2 ; off-sheet SSUSB_TXN  [also labelled SSUSB_TXN]
SS_TX_P: R67.2 ; off-sheet SSUSB_TXP  [also labelled SSUSB_TXP]
WOWWAN: R27.2 R28.1 U7.23(WOWWAN#)
NetD19_2: D19.2(K) R27.1
NetD20_2: D20.2(K) R32.2
NetR21_2: R21.2 U7.46(UIM2_RESET)
NetR22_2: R22.2 U7.44(UIM2_CLK)
NetR24_2: R24.2 U7.42(UIM2_DATA)
NetR33_1: R33.1 TP3.1
NetR37_1: R37.1 TP5.1

Not connected (* = marked no-connect by the designer): U7 1(CONFIG_3)* 8(W_DISABLE1#)* 12(Notch)* 13(Notch)* 14(Notch)* 15(Notch)* 16(Notch)* 17(Notch)* 18(Notch)* 19(Notch)* 20(I2S_CLK)* 21(CONFIG_0)* 22(I2S_RX)* 24(I2S_TX)* 25(DPR)* 26(W_DISABLE2#)* 28(I2S_WS)* 30(UIM1_RESET)* 32(UIM1_CLK)* 34(UIM1_DATA)* 36(UIM1_PWR)* 38(I2C_SCL(IO))* 41(PCIE_TX_M)* 43(PCIE_TX_P)* 47(PCIE_RX_M)* 49(PCIE_RX_P)* 50(PCIE_RST#)* 52(PCIE_CLKREQ#)* 53(PCIE_REFCLK_N)* 54(PCIE_WAKE#)* 55(PCIE_REFCLK_P)* 56(RFFE_SCLK)* 58(RFFE_SDATA)* 59(ANTCTL0)* 60(I2S_MCLK(IO))* 61(ANTCTL1)* 62(COEX2/UART_RX)* 63(ANTCTL2)* 64(COEX1/UART_TX)* 65(ANTCTL3)* 66(SIM1_DET(1.8V))* 68(I2C_SDA(IO))* 69(CONFIG_1)* 75(CONFIG_2)*

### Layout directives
differential pair: 4GUSB_D_N, 4GUSB_D_P, 5G_SSUSB_RX_N, 5G_SSUSB_RX_P, 5G_SSUSB_TX_N, 5G_SSUSB_TX_P, 5G_USB_TX_N, 5G_USB_TX_P

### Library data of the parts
C61 C62 = Cap Pol1: Polarized Capacitor (Radial)
C63-C66 = CAP1: C?
C67 C68 = C0402: PCB Footprint: C0201
D15 = Diode BAS70: Silicon AF Schottky Diode for High-Speed Switching; Note: Pin 2 is not connected and not drawn.
D19 D20 = LED0: 贴片发光二极管
R21 R22 R24 R25 R28 = Res2: Resistor
R27 = Res1: Resistor
R32 = R: 贴片电阻; 版权归属: 源创客
R33 R37 R64-R67 = RES2

## Sheet HLK-RM20-KIT-POWER_LED.SchDoc
size A3
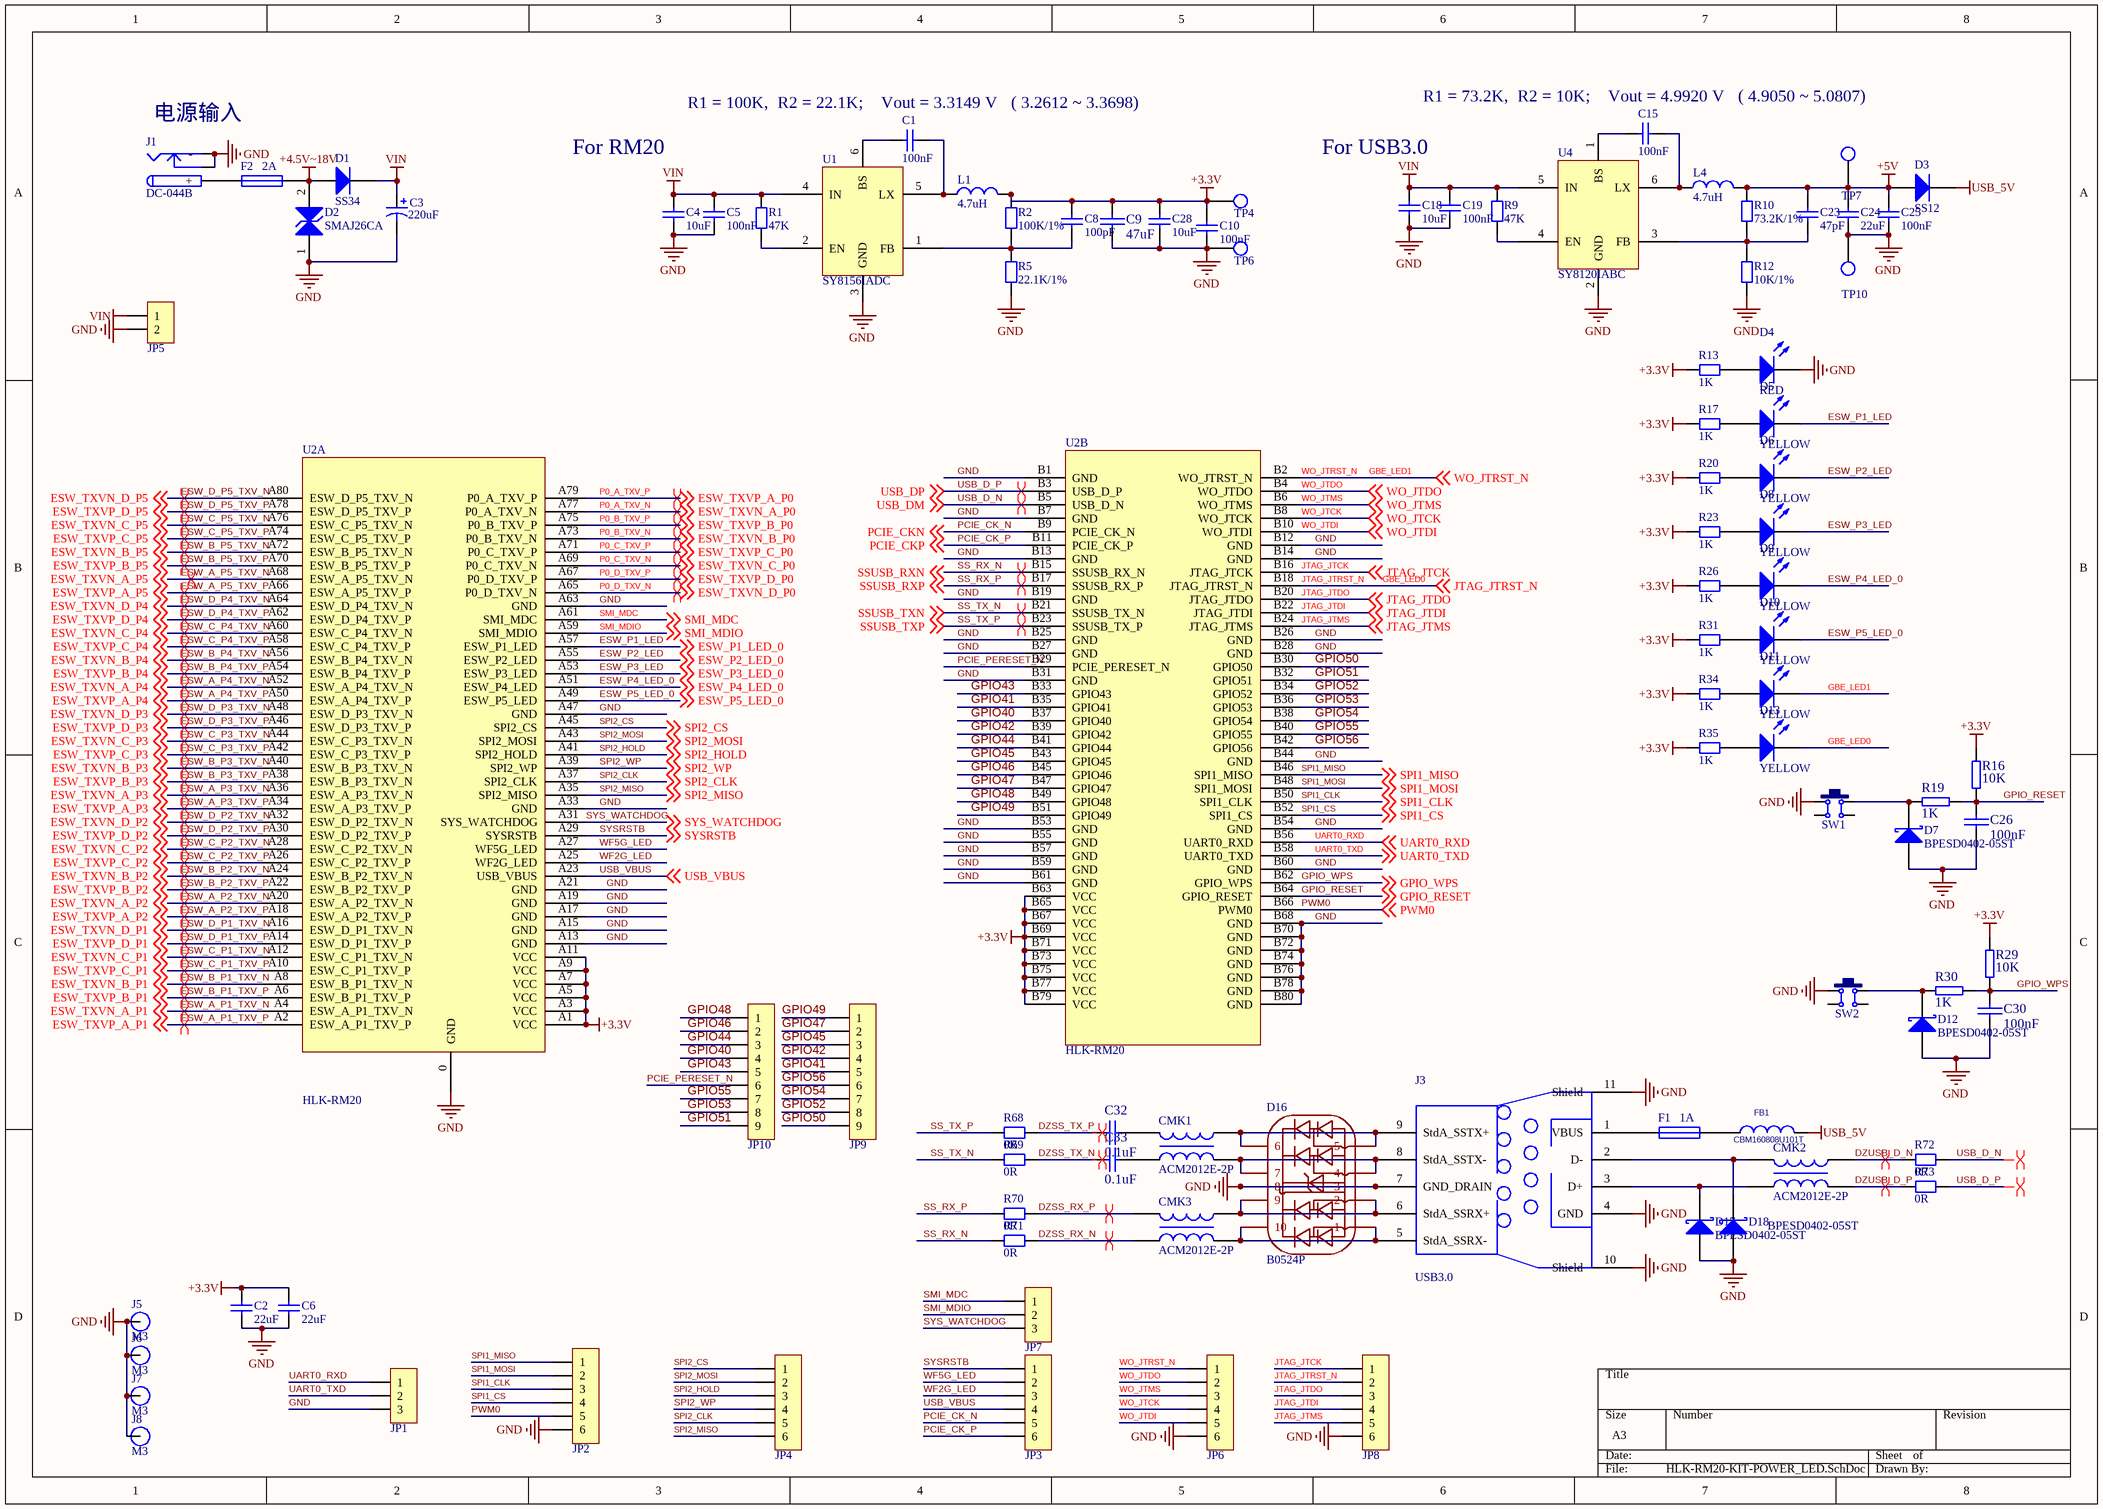
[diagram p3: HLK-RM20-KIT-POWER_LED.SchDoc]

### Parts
C1  100nF  [C 0402_L]
C2  22uF  [C 0805_L]
C3  220uF  [CT 8*12 - C]
C4  10uF  [C 0805_L]
C5  100nF  [C 0402_L]
C6  22uF  [C 0805_L]
C8  100pF  [C 0402_L]
C9  47uF  [C 1206_L]
C10  100nF  [C 0402_L]
C15  100nF  [C 0402_L]
C18  10uF  [C 0805_L]
C19  100nF  [C 0402_L]
C23  47pF  [C 0402_L]
C24  22uF  [C 0805_L]
C25  100nF  [C 0402_L]
C26  100nF  [C 0402_L]
C28  10uF  [C 0603_L]
C30  100nF  [C 0402_L]
C32  0.1uF  [C 0402_L]
C33  0.1uF  [C 0402_L]
CMK1  ACM2012E-2P  [SMD_4P]
CMK2  ACM2012E-2P  [SMD_4P]
CMK3  ACM2012E-2P  [SMD_4P]
D1  SS34  [SMB]
D2  SMAJ26CA  [DO-214AC]
D3  SS12  [SMA]
D4  RED  [LED 3MM-R]
D5  YELLOW  [LED 3MM-Y]
D6  YELLOW  [LED 3MM-Y]
D7  BPESD0402-05ST  [esd0402]
D8  YELLOW  [LED 3MM-Y]
D9  YELLOW  [LED 3MM-Y]
D10  YELLOW  [LED 3MM-Y]
D11  YELLOW  [LED 3MM-Y]
D12  BPESD0402-05ST  [esd0402]
D13  YELLOW  [LED 3MM-Y]
D16  B0524P  [DFN-10]
D17  BPESD0402-05ST  [ESD0402]
D18  BPESD0402-05ST  [ESD0402]
F1  1A  [FU 0603]
F2  2A  [FU 1206]
FB1  CBM160808U101T  [L 0603]
J1  DC-044B  [DC-005]
J3  USB3.0  [USB3.0-9P-DIP]
J5  M3  [M3 125X200]
J6  M3  [M3 125X200]
J7  M3  [M3 125X200]
J8  M3  [M3 125X200]
JP1  HDR-1X3  [HDR2.54-LI-3P]  (value not drawn)
JP2  HDR-1X6  [HDR2.54-LI-6P]  (value not drawn)
JP3  HDR-1X6  [HDR2.54-LI-6P]  (value not drawn)
JP4  HDR-1X6  [HDR2.54-LI-6P]  (value not drawn)
JP5  HDR-1X2  [XH2.54-LI-2P]  (value not drawn)
JP6  HDR-1X6  [HDR2.54-LI-6P]  (value not drawn)
JP7  HDR-1X3  [HDR2.54-LI-3P]  (value not drawn)
JP8  HDR-1X6  [HDR2.54-LI-6P]  (value not drawn)
JP9  HDR-1X9  [HDR2.0-LI-9P]  (value not drawn)
JP10  HDR-1X9  [HDR2.0-LI-9P]  (value not drawn)
L1  4.7uH  [L 6*6]
L4  4.7uH  [L 4*4]
R1  47K  [R 0402_L]
R2  100K/1%  [R 0402_L]
R5  22.1K/1%  [R 0402_L]
R9  47K  [R 0402_L]
R10  73.2K/1%  [R 0402_L]
R12  10K/1%  [R 0402_L]
R13  1K  [R 0402_L]
R16  10K  [R 0402_l]
R17  1K  [R 0402_L]
R19  1K  [R 0402_l]
R20  1K  [R 0402_L]
R23  1K  [R 0402_L]
R26  1K  [R 0402_L]
R29  10K  [R 0402_l]
R30  1K  [R 0402_l]
R31  1K  [R 0402_L]
R34  1K  [R 0402_L]
R35  1K  [R 0402_L]
R68  0R  [R 0402_L]
R69  0R  [R 0402_L]
R70  0R  [R 0402_L]
R71  0R  [R 0402_L]
R72  0R  [R 0402_L]
R73  0R  [R 0402_L]
SW1  6x6x5  [TSW DIP-4.5*4.5*3_V]  (value not drawn)
SW2  6x6x5  [TSW DIP-4.5*4.5*3_V]  (value not drawn)
TP4  测试点  [TEST 1.6]  (value not drawn)
TP6  测试点  [TEST 1.6]  (value not drawn)
TP7  测试点  [TEST 1.6]  (value not drawn)
TP10  测试点  [TEST 1.6]  (value not drawn)
U1  SY8156IADC  [SOT23-6N]
U2  HLK-RM20  [HLK-RM20]  (parts A,B of 2)
U4  SY8120IABC  [SOT23-6N]

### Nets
+3.3V: C2.2 C6.2 C8.2 C9.2 C10.1 C28.1 L1.2 R2.1 R13.2 R16.1 R17.2 R20.2 R23.2 R26.2 R29.1 R31.2 R34.2 R35.2 TP4.1 U2.A1(VCC) U2.A3(VCC) U2.A5(VCC) U2.A7(VCC) U2.A9(VCC) U2.A11(VCC) U2.B63(VCC) U2.B65(VCC) U2.B67(VCC) U2.B69(VCC) U2.B71(VCC) U2.B73(VCC) U2.B75(VCC) U2.B77(VCC) U2.B79(VCC)
+4.5V~18V: D1.1(A) D2.2 F2.2
+5V: C23.2 C24.2 C25.1 D3.1(A) L4.2 R10.1 TP7.1
GND: C2.1 C3.2 C4.1 C5.2 C6.1 C9.1 C10.2 C18.1 C19.2 C24.1 C25.2 C26.1 C28.2 C30.1 D2.1 D4.2(K) D7.1(A) D12.1(A) D16.3 D16.8 D17.1(A) D18.1(A) J1.2(-) J1.3 J3.4(GND) J3.7(GND_DRAIN) J3.10(Shield) J3.11(Shield) J5.1(GND) J6.1(GND) J7.1(GND) J8.1(GND) JP1.3 JP2.6 JP5.2 JP6.6 JP8.6 R5.2 R12.2 SW1.1 SW2.1 TP6.1 TP10.1 U1.3(GND) U2.0(GND) U2.A13(GND) U2.A15(GND) U2.A17(GND) U2.A19(GND) U2.A21(GND) U2.A33(GND) U2.A47(GND) U2.A63(GND) U2.B1(GND) U2.B7(GND) U2.B12(GND) U2.B13(GND) U2.B14(GND) U2.B19(GND) U2.B25(GND) U2.B26(GND) U2.B27(GND) U2.B28(GND) U2.B31(GND) U2.B44(GND) U2.B53(GND) U2.B54(GND) U2.B55(GND) U2.B57(GND) U2.B59(GND) U2.B60(GND) U2.B61(GND) U2.B68(GND) U2.B70(GND) U2.B72(GND) U2.B74(GND) U2.B76(GND) U2.B78(GND) U2.B80(GND) U4.2(GND)
USB_5V: D3.2(K) FB1.1
VIN: C3.1 C4.2 C5.1 C18.2 C19.1 D1.2(K) JP5.1 R1.1 R9.1 U1.4(IN) U4.5(IN)
DZSS_RX_N: CMK3.1 R71.1
DZSS_RX_P: CMK3.2 R70.1
DZSS_TX_N: C33.2 R69.1
DZSS_TX_P: C32.2 R68.1
DZUSB_D_N: CMK2.3 R72.2
DZUSB_D_P: CMK2.4 R73.2
ESW_A_P1_TXV_N: U2.A4(ESW_A_P1_TXV_N) ; off-sheet ESW_TXVN_A_P1  [also labelled ESW_TXVN_A_P1]
ESW_A_P1_TXV_P: U2.A2(ESW_A_P1_TXV_P) ; off-sheet ESW_TXVP_A_P1  [also labelled ESW_TXVP_A_P1]
ESW_A_P2_TXV_N: U2.A20(ESW_A_P2_TXV_N) ; off-sheet ESW_TXVN_A_P2  [also labelled ESW_TXVN_A_P2]
ESW_A_P2_TXV_P: U2.A18(ESW_A_P2_TXV_P) ; off-sheet ESW_TXVP_A_P2  [also labelled ESW_TXVP_A_P2]
ESW_A_P3_TXV_N: U2.A36(ESW_A_P3_TXV_N) ; off-sheet ESW_TXVN_A_P3  [also labelled ESW_TXVN_A_P3]
ESW_A_P3_TXV_P: U2.A34(ESW_A_P3_TXV_P) ; off-sheet ESW_TXVP_A_P3  [also labelled ESW_TXVP_A_P3]
ESW_A_P4_TXV_N: U2.A52(ESW_A_P4_TXV_N) ; off-sheet ESW_TXVN_A_P4  [also labelled ESW_TXVN_A_P4]
ESW_A_P4_TXV_P: U2.A50(ESW_A_P4_TXV_P) ; off-sheet ESW_TXVP_A_P4  [also labelled ESW_TXVP_A_P4]
ESW_A_P5_TXV_N: U2.A68(ESW_A_P5_TXV_N) ; off-sheet ESW_TXVN_A_P5  [also labelled ESW_TXVN_A_P5]
ESW_A_P5_TXV_P: U2.A66(ESW_A_P5_TXV_P) ; off-sheet ESW_TXVP_A_P5  [also labelled ESW_TXVP_A_P5]
ESW_B_P1_TXV_N: U2.A8(ESW_B_P1_TXV_N) ; off-sheet ESW_TXVN_B_P1  [also labelled ESW_TXVN_B_P1]
ESW_B_P1_TXV_P: U2.A6(ESW_B_P1_TXV_P) ; off-sheet ESW_TXVP_B_P1  [also labelled ESW_TXVP_B_P1]
ESW_B_P2_TXV_N: U2.A24(ESW_B_P2_TXV_N) ; off-sheet ESW_TXVN_B_P2  [also labelled ESW_TXVN_B_P2]
ESW_B_P2_TXV_P: U2.A22(ESW_B_P2_TXV_P) ; off-sheet ESW_TXVP_B_P2  [also labelled ESW_TXVP_B_P2]
ESW_B_P3_TXV_N: U2.A40(ESW_B_P3_TXV_N) ; off-sheet ESW_TXVN_B_P3  [also labelled ESW_TXVN_B_P3]
ESW_B_P3_TXV_P: U2.A38(ESW_B_P3_TXV_N) ; off-sheet ESW_TXVP_B_P3  [also labelled ESW_TXVP_B_P3]
ESW_B_P4_TXV_N: U2.A56(ESW_B_P4_TXV_N) ; off-sheet ESW_TXVN_B_P4  [also labelled ESW_TXVN_B_P4]
ESW_B_P4_TXV_P: U2.A54(ESW_B_P4_TXV_P) ; off-sheet ESW_TXVP_B_P4  [also labelled ESW_TXVP_B_P4]
ESW_B_P5_TXV_N: U2.A72(ESW_B_P5_TXV_N) ; off-sheet ESW_TXVN_B_P5  [also labelled ESW_TXVN_B_P5]
ESW_B_P5_TXV_P: U2.A70(ESW_B_P5_TXV_P) ; off-sheet ESW_TXVP_B_P5  [also labelled ESW_TXVP_B_P5]
ESW_C_P1_TXV_N: U2.A12(ESW_C_P1_TXV_N) ; off-sheet ESW_TXVN_C_P1  [also labelled ESW_TXVN_C_P1]
ESW_C_P1_TXV_P: U2.A10(ESW_C_P1_TXV_P) ; off-sheet ESW_TXVP_C_P1  [also labelled ESW_TXVP_C_P1]
ESW_C_P2_TXV_N: U2.A28(ESW_C_P2_TXV_N) ; off-sheet ESW_TXVN_C_P2  [also labelled ESW_TXVN_C_P2]
ESW_C_P2_TXV_P: U2.A26(ESW_C_P2_TXV_P) ; off-sheet ESW_TXVP_C_P2  [also labelled ESW_TXVP_C_P2]
ESW_C_P3_TXV_N: U2.A44(ESW_C_P3_TXV_N) ; off-sheet ESW_TXVN_C_P3  [also labelled ESW_TXVN_C_P3]
ESW_C_P3_TXV_P: U2.A42(ESW_C_P3_TXV_P) ; off-sheet ESW_TXVP_C_P3  [also labelled ESW_TXVP_C_P3]
ESW_C_P4_TXV_N: U2.A60(ESW_C_P4_TXV_N) ; off-sheet ESW_TXVN_C_P4  [also labelled ESW_TXVN_C_P4]
ESW_C_P4_TXV_P: U2.A58(ESW_C_P4_TXV_P) ; off-sheet ESW_TXVP_C_P4  [also labelled ESW_TXVP_C_P4]
ESW_C_P5_TXV_N: U2.A76(ESW_C_P5_TXV_N) ; off-sheet ESW_TXVN_C_P5  [also labelled ESW_TXVN_C_P5]
ESW_C_P5_TXV_P: U2.A74(ESW_C_P5_TXV_P) ; off-sheet ESW_TXVP_C_P5  [also labelled ESW_TXVP_C_P5]
ESW_D_P1_TXV_N: U2.A16(ESW_D_P1_TXV_N) ; off-sheet ESW_TXVN_D_P1  [also labelled ESW_TXVN_D_P1]
ESW_D_P1_TXV_P: U2.A14(ESW_D_P1_TXV_P) ; off-sheet ESW_TXVP_D_P1  [also labelled ESW_TXVP_D_P1]
ESW_D_P2_TXV_N: U2.A32(ESW_D_P2_TXV_N) ; off-sheet ESW_TXVN_D_P2  [also labelled ESW_TXVN_D_P2]
ESW_D_P2_TXV_P: U2.A30(ESW_D_P2_TXV_P) ; off-sheet ESW_TXVP_D_P2  [also labelled ESW_TXVP_D_P2]
ESW_D_P3_TXV_N: U2.A48(ESW_D_P3_TXV_N) ; off-sheet ESW_TXVN_D_P3  [also labelled ESW_TXVN_D_P3]
ESW_D_P3_TXV_P: U2.A46(ESW_D_P3_TXV_P) ; off-sheet ESW_TXVP_D_P3  [also labelled ESW_TXVP_D_P3]
ESW_D_P4_TXV_N: U2.A64(ESW_D_P4_TXV_N) ; off-sheet ESW_TXVN_D_P4  [also labelled ESW_TXVN_D_P4]
ESW_D_P4_TXV_P: U2.A62(ESW_D_P4_TXV_P) ; off-sheet ESW_TXVP_D_P4  [also labelled ESW_TXVP_D_P4]
ESW_D_P5_TXV_N: U2.A80(ESW_D_P5_TXV_N) ; off-sheet ESW_TXVN_D_P5  [also labelled ESW_TXVN_D_P5]
ESW_D_P5_TXV_P: U2.A78(ESW_D_P5_TXV_P) ; off-sheet ESW_TXVP_D_P5  [also labelled ESW_TXVP_D_P5]
ESW_P1_LED: D5.2(K) U2.A57(ESW_P1_LED) ; off-sheet ESW_P1_LED_0  [also labelled ESW_P1_LED_0]
ESW_P2_LED: D6.2(K) U2.A55(ESW_P2_LED) ; off-sheet ESW_P2_LED_0  [also labelled ESW_P2_LED_0]
ESW_P3_LED: D8.2(K) U2.A53(ESW_P3_LED) ; off-sheet ESW_P3_LED_0  [also labelled ESW_P3_LED_0]
ESW_P4_LED_0: D9.2(K) U2.A51(ESW_P4_LED) ; off-sheet ESW_P4_LED_0
ESW_P5_LED_0: D10.2(K) U2.A49(ESW_P5_LED) ; off-sheet ESW_P5_LED_0
GBE_LED0: D13.2(K) JP8.2 U2.B18(JTAG_JTRST_N) ; off-sheet JTAG_JTRST_N  [also labelled JTAG_JTRST_N]
GBE_LED1: D11.2(K) JP6.1 U2.B2(WO_JTRST_N) ; off-sheet WO_JTRST_N  [also labelled WO_JTRST_N]
GPIO40: JP10.4 U2.B37(GPIO40)
GPIO41: JP9.5 U2.B35(GPIO41)
GPIO42: JP9.4 U2.B39(GPIO42)
GPIO43: JP10.5 U2.B33(GPIO43)
GPIO44: JP10.3 U2.B41(GPIO44)
GPIO45: JP9.3 U2.B43(GPIO45)
GPIO46: JP10.2 U2.B45(GPIO46)
GPIO47: JP9.2 U2.B47(GPIO47)
GPIO48: JP10.1 U2.B49(GPIO48)
GPIO49: JP9.1 U2.B51(GPIO49)
GPIO50: JP9.9 U2.B30(GPIO50)
GPIO51: JP10.9 U2.B32(GPIO51)
GPIO52: JP9.8 U2.B34(GPIO52)
GPIO53: JP10.8 U2.B36(GPIO53)
GPIO54: JP9.7 U2.B38(GPIO54)
GPIO55: JP10.7 U2.B40(GPIO55)
GPIO56: JP9.6 U2.B42(GPIO56)
GPIO_RESET: C26.2 R16.2 R19.2 U2.B64(GPIO_RESET) ; off-sheet GPIO_RESET
GPIO_WPS: C30.2 R29.2 R30.2 U2.B62(GPIO_WPS) ; off-sheet GPIO_WPS
JTAG_JTCK: JP8.1 U2.B16(JTAG_JTCK) ; off-sheet JTAG_JTCK
JTAG_JTDI: JP8.4 U2.B22(JTAG_JTDI) ; off-sheet JTAG_JTDI
JTAG_JTDO: JP8.3 U2.B20(JTAG_JTDO) ; off-sheet JTAG_JTDO
JTAG_JTMS: JP8.5 U2.B24(JTAG_JTMS) ; off-sheet JTAG_JTMS
P0_A_TXV_N: U2.A77(P0_A_TXV_N) ; off-sheet ESW_TXVN_A_P0  [also labelled ESW_TXVN_A_P0]
P0_A_TXV_P: U2.A79(P0_A_TXV_P) ; off-sheet ESW_TXVP_A_P0  [also labelled ESW_TXVP_A_P0]
P0_B_TXV_N: U2.A73(P0_B_TXV_N) ; off-sheet ESW_TXVN_B_P0  [also labelled ESW_TXVN_B_P0]
P0_B_TXV_P: U2.A75(P0_B_TXV_P) ; off-sheet ESW_TXVP_B_P0  [also labelled ESW_TXVP_B_P0]
P0_C_TXV_N: U2.A69(P0_C_TXV_N) ; off-sheet ESW_TXVN_C_P0  [also labelled ESW_TXVN_C_P0]
P0_C_TXV_P: U2.A71(P0_C_TXV_P) ; off-sheet ESW_TXVP_C_P0  [also labelled ESW_TXVP_C_P0]
P0_D_TXV_N: U2.A65(P0_D_TXV_N) ; off-sheet ESW_TXVN_D_P0  [also labelled ESW_TXVN_D_P0]
P0_D_TXV_P: U2.A67(P0_D_TXV_P) ; off-sheet ESW_TXVP_D_P0  [also labelled ESW_TXVP_D_P0]
PCIE_CK_N: JP3.5 U2.B9(PCIE_CK_N) ; off-sheet PCIE_CKN  [also labelled PCIE_CKN]
PCIE_CK_P: JP3.6 U2.B11(PCIE_CK_P) ; off-sheet PCIE_CKP  [also labelled PCIE_CKP]
PCIE_PERESET_N: JP10.6 U2.B29(PCIE_PERESET_N)
PWM0: JP2.5 U2.B66(PWM0) ; off-sheet PWM0
SMI_MDC: JP7.1 U2.A61(SMI_MDC) ; off-sheet SMI_MDC
SMI_MDIO: JP7.2 U2.A59(SMI_MDIO) ; off-sheet SMI_MDIO
SPI1_CLK: JP2.3 U2.B50(SPI1_CLK) ; off-sheet SPI1_CLK
SPI1_CS: JP2.4 U2.B52(SPI1_CS) ; off-sheet SPI1_CS
SPI1_MISO: JP2.1 U2.B46(SPI1_MISO) ; off-sheet SPI1_MISO  [project net PERST_4G]
SPI1_MOSI: JP2.2 U2.B48(SPI1_MOSI) ; off-sheet SPI1_MOSI  [project net FULL_CARD_POWER_OFF#]
SPI2_CLK: JP4.5 U2.A37(SPI2_CLK) ; off-sheet SPI2_CLK
SPI2_CS: JP4.1 U2.A45(SPI2_CS) ; off-sheet SPI2_CS
SPI2_HOLD: JP4.3 U2.A41(SPI2_HOLD) ; off-sheet SPI2_HOLD
SPI2_MISO: JP4.6 U2.A35(SPI2_MISO) ; off-sheet SPI2_MISO
SPI2_MOSI: JP4.2 U2.A43(SPI2_MOSI) ; off-sheet SPI2_MOSI
SPI2_WP: JP4.4 U2.A39(SPI2_WP) ; off-sheet SPI2_WP
SS_RX_N: R71.2 U2.B15(SSUSB_RX_N) ; off-sheet SSUSB_RXN  [also labelled SSUSB_RXN]
SS_RX_P: R70.2 U2.B17(SSUSB_RX_P) ; off-sheet SSUSB_RXP  [also labelled SSUSB_RXP]
SS_TX_N: R69.2 U2.B21(SSUSB_TX_N) ; off-sheet SSUSB_TXN  [also labelled SSUSB_TXN]
SS_TX_P: R68.2 U2.B23(SSUSB_TX_P) ; off-sheet SSUSB_TXP  [also labelled SSUSB_TXP]
SYS_WATCHDOG: JP7.3 U2.A31(SYS_WATCHDOG) ; off-sheet SYS_WATCHDOG
SYSRSTB: JP3.1 U2.A29(SYSRSTB) ; off-sheet SYSRSTB
UART0_RXD: JP1.1 U2.B56(UART0_RXD) ; off-sheet UART0_RXD
UART0_TXD: JP1.2 U2.B58(UART0_TXD) ; off-sheet UART0_TXD
USB_D_N: R72.1 U2.B5(USB_D_N) ; off-sheet USB_DM  [also labelled USB_DM]
USB_D_P: R73.1 U2.B3(USB_D_P) ; off-sheet USB_DP  [also labelled USB_DP]
USB_VBUS: JP3.4 U2.A23(USB_VBUS) ; off-sheet USB_VBUS
WF2G_LED: JP3.3 U2.A25(WF2G_LED)
WF5G_LED: JP3.2 U2.A27(WF5G_LED)
WO_JTCK: JP6.4 U2.B8(WO_JTCK) ; off-sheet WO_JTCK
WO_JTDI: JP6.5 U2.B10(WO_JTDI) ; off-sheet WO_JTDI
WO_JTDO: JP6.2 U2.B4(WO_JTDO) ; off-sheet WO_JTDO
WO_JTMS: JP6.3 U2.B6(WO_JTMS) ; off-sheet WO_JTMS
NetC1_1: C1.1 U1.6(BS)
NetC1_2: C1.2 L1.1 U1.5(LX)
NetC8_1: C8.1 R2.2 R5.1 U1.1(FB)
NetC15_1: C15.1 U4.1(BS)
NetC15_2: C15.2 L4.1 U4.6(LX)
NetC23_1: C23.1 R10.2 R12.1 U4.3(FB)
NetC32_1: C32.1 CMK1.2
NetC33_1: C33.1 CMK1.1
NetCMK1_3: CMK1.3 D16.5 D16.6 J3.9(StdA_SSTX+)
NetCMK1_4: CMK1.4 D16.4 D16.7 J3.8(StdA_SSTX-)
NetCMK2_1: CMK2.1 D17.2(K) J3.3(D+)
NetCMK2_2: CMK2.2 D18.2(K) J3.2(D-)
NetCMK3_3: CMK3.3 D16.2 D16.9 J3.6(StdA_SSRX+)
NetCMK3_4: CMK3.4 D16.1 D16.10 J3.5(StdA_SSRX-)
NetD4_1: D4.1(A) R13.1
NetD5_1: D5.1(A) R17.1
NetD6_1: D6.1(A) R20.1
NetD7_2: D7.2(K) R19.1 SW1.2
NetD8_1: D8.1(A) R23.1
NetD9_1: D9.1(A) R26.1
NetD10_1: D10.1(A) R31.1
NetD11_1: D11.1(A) R34.1
NetD12_2: D12.2(K) R30.1 SW2.2
NetD13_1: D13.1(A) R35.1
NetF1_1: F1.1 J3.1(VBUS)
NetF1_2: F1.2 FB1.2
NetF2_1: F2.1 J1.1(+)
NetR1_2: R1.2 U1.2(EN)
NetR9_2: R9.2 U4.4(EN)

Not connected (* = marked no-connect by the designer): SW1 3 4; SW2 3 4

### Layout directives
differential pair: DZSS_RX_N, DZSS_RX_P, DZSS_TX_N, DZSS_TX_P, DZUSB_D_N, DZUSB_D_P, ESW_A_P1_TXV_N, ESW_A_P1_TXV_P, ESW_A_P2_TXV_N, ESW_A_P2_TXV_P, ESW_A_P3_TXV_N, ESW_A_P3_TXV_P, ESW_A_P4_TXV_N, ESW_A_P4_TXV_P, ESW_A_P5_TXV_N, ESW_A_P5_TXV_P, ESW_B_P1_TXV_N, ESW_B_P1_TXV_P, ESW_B_P2_TXV_N, ESW_B_P2_TXV_P, ESW_B_P3_TXV_N, ESW_B_P3_TXV_P, ESW_B_P4_TXV_N, ESW_B_P4_TXV_P, ESW_B_P5_TXV_N, ESW_B_P5_TXV_P, ESW_C_P1_TXV_N, ESW_C_P1_TXV_P, ESW_C_P2_TXV_N, ESW_C_P2_TXV_P, ESW_C_P3_TXV_N, ESW_C_P3_TXV_P, ESW_C_P4_TXV_N, ESW_C_P4_TXV_P, ESW_C_P5_TXV_N, ESW_C_P5_TXV_P, ESW_D_P1_TXV_N, ESW_D_P1_TXV_P, ESW_D_P2_TXV_N, ESW_D_P2_TXV_P, ESW_D_P3_TXV_N, ESW_D_P3_TXV_P, ESW_D_P4_TXV_N, ESW_D_P4_TXV_P, ESW_D_P5_TXV_N, ESW_D_P5_TXV_P, P0_A_TXV_N, P0_A_TXV_P, P0_B_TXV_N, P0_B_TXV_P, P0_C_TXV_N, P0_C_TXV_P, P0_D_TXV_N, P0_D_TXV_P, SS_RX_N, SS_RX_P, SS_TX_N, SS_TX_P, USB_D_N, USB_D_P

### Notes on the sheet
- (near C1) R1 = 100K,  R2 = 22.1K;    Vout = 3.3149 V   ( 3.2612 ~ 3.3698)
- (near C15) R1 = 73.2K,  R2 = 10K;    Vout = 4.9920 V   ( 4.9050 ~ 5.0807)
- (near J1) 电源输入
- For RM20
- For USB3.0

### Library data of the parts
C1 C5 C10 C15 C19 C25 C28 = Cap: as C7 on sheet HLK-RM20-KIT-4G
C2 C4 C6 C18 C23 C24 = Cap: as C14 on sheet HLK-RM20-KIT-4G
C3 = Cap Pol1: Polarized Capacitor (Radial)
C8 = Cap: as C20 on sheet HLK-RM20-KIT-4G
C9 C26 C30 C32 C33 = CAP: Capacitor
CMK1-CMK3 = CMK1
D1 D3 = Diode: Default Diode
D2 = TVS
D4-D6 D8-D11 D13 = LED0: 贴片发光二极管
D7 D12 D17 D18 = Diode BAS70: as D15 on sheet HLK-RM20-KIT-5G
F1 F2 = Fuse 1: Fuse
FB1 = INDUCTOR: MFR_Name: MURATA; MFR_PN: BLM15PX121SZ1D
J1 = DC-044B: Low Voltage Power Supply Connector
J5-J8 = M3: 铜柱孔; 版权归属: 源创客
JP1 JP7 = Header 3: 3P接插件; 版权归属: 源创客
JP2-JP4 JP6 JP8 = Header 6: 6P接插件; 版权归属: 源创客
JP5 = Header 2: 2P接插件; 版权归属: 源创客
JP9 JP10 = Header 9: 9P接插件; 版权归属: 源创客
L1 L4 = LineInductors
R1 R2 R5 R9 R10 R12 R13 R17 R20 R23 R26 R31 R34 R35 R68-R73 = R: 贴片电阻; 版权归属: 源创客
R16 R19 R29 R30 = RES2
SW1 SW2 = TSW DIP-6x6: 直插6x6轻触开关; 版权归属: 源创客
TP4 TP6 TP7 TP10 = TP
U1 = SY8105
U4 = SY8201

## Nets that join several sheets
+3.3V: HLK-RM20-KIT-4G (D14.1), HLK-RM20-KIT-5G (D19.1 D20.1 R28.2), HLK-RM20-KIT-POWER_LED (34 pins)
+3.8V: HLK-RM20-KIT-4G (13 pins), HLK-RM20-KIT-5G (12 pins)
GND: HLK-RM20-KIT-RJ45 (28 pins), HLK-RM20-KIT-4G (38 pins), HLK-RM20-KIT-5G (21 pins), HLK-RM20-KIT-POWER_LED (80 pins)
SIM2_VDD: HLK-RM20-KIT-4G (5 pins), HLK-RM20-KIT-5G (R25.1 U7.48)
VIN: HLK-RM20-KIT-4G (C14.2 C16.1 R4.1 U5.5), HLK-RM20-KIT-POWER_LED (11 pins)
4GUSB_D_N: HLK-RM20-KIT-4G (R18.1 R63.2), HLK-RM20-KIT-5G (R33.2 U7.9)
4GUSB_D_P: HLK-RM20-KIT-4G (R15.1 R36.2), HLK-RM20-KIT-5G (R37.2 U7.7)
ESW_A_P1_TXV_N: HLK-RM20-KIT-RJ45 (T3.23), HLK-RM20-KIT-POWER_LED (U2.A4)
ESW_A_P1_TXV_P: HLK-RM20-KIT-RJ45 (T3.24), HLK-RM20-KIT-POWER_LED (U2.A2)
ESW_A_P2_TXV_N: HLK-RM20-KIT-RJ45 (T3.11), HLK-RM20-KIT-POWER_LED (U2.A20)
ESW_A_P2_TXV_P: HLK-RM20-KIT-RJ45 (T3.12), HLK-RM20-KIT-POWER_LED (U2.A18)
ESW_A_P3_TXV_N: HLK-RM20-KIT-RJ45 (T2.23), HLK-RM20-KIT-POWER_LED (U2.A36)
ESW_A_P3_TXV_P: HLK-RM20-KIT-RJ45 (T2.24), HLK-RM20-KIT-POWER_LED (U2.A34)
ESW_A_P4_TXV_N: HLK-RM20-KIT-RJ45 (T2.11), HLK-RM20-KIT-POWER_LED (U2.A52)
ESW_A_P4_TXV_P: HLK-RM20-KIT-RJ45 (T2.12), HLK-RM20-KIT-POWER_LED (U2.A50)
ESW_A_P5_TXV_N: HLK-RM20-KIT-RJ45 (T1.23), HLK-RM20-KIT-POWER_LED (U2.A68)
ESW_A_P5_TXV_P: HLK-RM20-KIT-RJ45 (T1.24), HLK-RM20-KIT-POWER_LED (U2.A66)
ESW_B_P1_TXV_N: HLK-RM20-KIT-RJ45 (T3.20), HLK-RM20-KIT-POWER_LED (U2.A8)
ESW_B_P1_TXV_P: HLK-RM20-KIT-RJ45 (T3.21), HLK-RM20-KIT-POWER_LED (U2.A6)
ESW_B_P2_TXV_N: HLK-RM20-KIT-RJ45 (T3.8), HLK-RM20-KIT-POWER_LED (U2.A24)
ESW_B_P2_TXV_P: HLK-RM20-KIT-RJ45 (T3.9), HLK-RM20-KIT-POWER_LED (U2.A22)
ESW_B_P3_TXV_N: HLK-RM20-KIT-RJ45 (T2.20), HLK-RM20-KIT-POWER_LED (U2.A40)
ESW_B_P3_TXV_P: HLK-RM20-KIT-RJ45 (T2.21), HLK-RM20-KIT-POWER_LED (U2.A38)
ESW_B_P4_TXV_N: HLK-RM20-KIT-RJ45 (T2.8), HLK-RM20-KIT-POWER_LED (U2.A56)
ESW_B_P4_TXV_P: HLK-RM20-KIT-RJ45 (T2.9), HLK-RM20-KIT-POWER_LED (U2.A54)
ESW_B_P5_TXV_N: HLK-RM20-KIT-RJ45 (T1.20), HLK-RM20-KIT-POWER_LED (U2.A72)
ESW_B_P5_TXV_P: HLK-RM20-KIT-RJ45 (T1.21), HLK-RM20-KIT-POWER_LED (U2.A70)
ESW_C_P1_TXV_N: HLK-RM20-KIT-RJ45 (T3.17), HLK-RM20-KIT-POWER_LED (U2.A12)
ESW_C_P1_TXV_P: HLK-RM20-KIT-RJ45 (T3.18), HLK-RM20-KIT-POWER_LED (U2.A10)
ESW_C_P2_TXV_N: HLK-RM20-KIT-RJ45 (T3.5), HLK-RM20-KIT-POWER_LED (U2.A28)
ESW_C_P2_TXV_P: HLK-RM20-KIT-RJ45 (T3.6), HLK-RM20-KIT-POWER_LED (U2.A26)
ESW_C_P3_TXV_N: HLK-RM20-KIT-RJ45 (T2.17), HLK-RM20-KIT-POWER_LED (U2.A44)
ESW_C_P3_TXV_P: HLK-RM20-KIT-RJ45 (T2.18), HLK-RM20-KIT-POWER_LED (U2.A42)
ESW_C_P4_TXV_N: HLK-RM20-KIT-RJ45 (T2.5), HLK-RM20-KIT-POWER_LED (U2.A60)
ESW_C_P4_TXV_P: HLK-RM20-KIT-RJ45 (T2.6), HLK-RM20-KIT-POWER_LED (U2.A58)
ESW_C_P5_TXV_N: HLK-RM20-KIT-RJ45 (T1.17), HLK-RM20-KIT-POWER_LED (U2.A76)
ESW_C_P5_TXV_P: HLK-RM20-KIT-RJ45 (T1.18), HLK-RM20-KIT-POWER_LED (U2.A74)
ESW_D_P1_TXV_N: HLK-RM20-KIT-RJ45 (T3.14), HLK-RM20-KIT-POWER_LED (U2.A16)
ESW_D_P1_TXV_P: HLK-RM20-KIT-RJ45 (T3.15), HLK-RM20-KIT-POWER_LED (U2.A14)
ESW_D_P2_TXV_N: HLK-RM20-KIT-RJ45 (T3.2), HLK-RM20-KIT-POWER_LED (U2.A32)
ESW_D_P2_TXV_P: HLK-RM20-KIT-RJ45 (T3.3), HLK-RM20-KIT-POWER_LED (U2.A30)
ESW_D_P3_TXV_N: HLK-RM20-KIT-RJ45 (T2.14), HLK-RM20-KIT-POWER_LED (U2.A48)
ESW_D_P3_TXV_P: HLK-RM20-KIT-RJ45 (T2.15), HLK-RM20-KIT-POWER_LED (U2.A46)
ESW_D_P4_TXV_N: HLK-RM20-KIT-RJ45 (T2.2), HLK-RM20-KIT-POWER_LED (U2.A64)
ESW_D_P4_TXV_P: HLK-RM20-KIT-RJ45 (T2.3), HLK-RM20-KIT-POWER_LED (U2.A62)
ESW_D_P5_TXV_N: HLK-RM20-KIT-RJ45 (T1.14), HLK-RM20-KIT-POWER_LED (U2.A80)
ESW_D_P5_TXV_P: HLK-RM20-KIT-RJ45 (T1.15), HLK-RM20-KIT-POWER_LED (U2.A78)
FULL_CARD_POWER_OFF#: HLK-RM20-KIT-5G (U7.6), HLK-RM20-KIT-POWER_LED (JP2.2 U2.B48)
P0_A_TXV_N: HLK-RM20-KIT-RJ45 (T1.11), HLK-RM20-KIT-POWER_LED (U2.A77)
P0_A_TXV_P: HLK-RM20-KIT-RJ45 (T1.12), HLK-RM20-KIT-POWER_LED (U2.A79)
P0_B_TXV_N: HLK-RM20-KIT-RJ45 (T1.8), HLK-RM20-KIT-POWER_LED (U2.A73)
P0_B_TXV_P: HLK-RM20-KIT-RJ45 (T1.9), HLK-RM20-KIT-POWER_LED (U2.A75)
P0_C_TXV_N: HLK-RM20-KIT-RJ45 (T1.5), HLK-RM20-KIT-POWER_LED (U2.A69)
P0_C_TXV_P: HLK-RM20-KIT-RJ45 (T1.6), HLK-RM20-KIT-POWER_LED (U2.A71)
P0_D_TXV_N: HLK-RM20-KIT-RJ45 (T1.2), HLK-RM20-KIT-POWER_LED (U2.A65)
P0_D_TXV_P: HLK-RM20-KIT-RJ45 (T1.3), HLK-RM20-KIT-POWER_LED (U2.A67)
PERST#: HLK-RM20-KIT-4G (Q1.3 U6.33), HLK-RM20-KIT-5G (U7.67)
PERST_4G: HLK-RM20-KIT-4G (R11.2), HLK-RM20-KIT-POWER_LED (JP2.1 U2.B46)
SIM2_CLK: HLK-RM20-KIT-4G (C12.1 TVS1.3 U3.4 U6.12), HLK-RM20-KIT-5G (R22.1)
SIM2_DATA: HLK-RM20-KIT-4G (5 pins), HLK-RM20-KIT-5G (R24.1)
SIM2_RST: HLK-RM20-KIT-4G (C11.1 TVS1.4 U3.5 U6.14), HLK-RM20-KIT-5G (R21.1)
SS_RX_N: HLK-RM20-KIT-5G (R64.2), HLK-RM20-KIT-POWER_LED (R71.2 U2.B15)
SS_RX_P: HLK-RM20-KIT-5G (R65.2), HLK-RM20-KIT-POWER_LED (R70.2 U2.B17)
SS_TX_N: HLK-RM20-KIT-5G (R66.2), HLK-RM20-KIT-POWER_LED (R69.2 U2.B21)
SS_TX_P: HLK-RM20-KIT-5G (R67.2), HLK-RM20-KIT-POWER_LED (R68.2 U2.B23)
USB_D_N: HLK-RM20-KIT-4G (R18.2), HLK-RM20-KIT-POWER_LED (R72.1 U2.B5)
USB_D_P: HLK-RM20-KIT-4G (R15.2), HLK-RM20-KIT-POWER_LED (R73.1 U2.B3)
